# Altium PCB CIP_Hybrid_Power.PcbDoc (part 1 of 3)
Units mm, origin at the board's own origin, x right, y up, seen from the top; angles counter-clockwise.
Board outline 70 x 70 mm, 4 copper layers (Top Layer, GND Pour Layer, Signal Layer 1, Bottom Layer), stack 1.68 mm thick; 202 components, 120 nets, 578 pads, 363 vias.
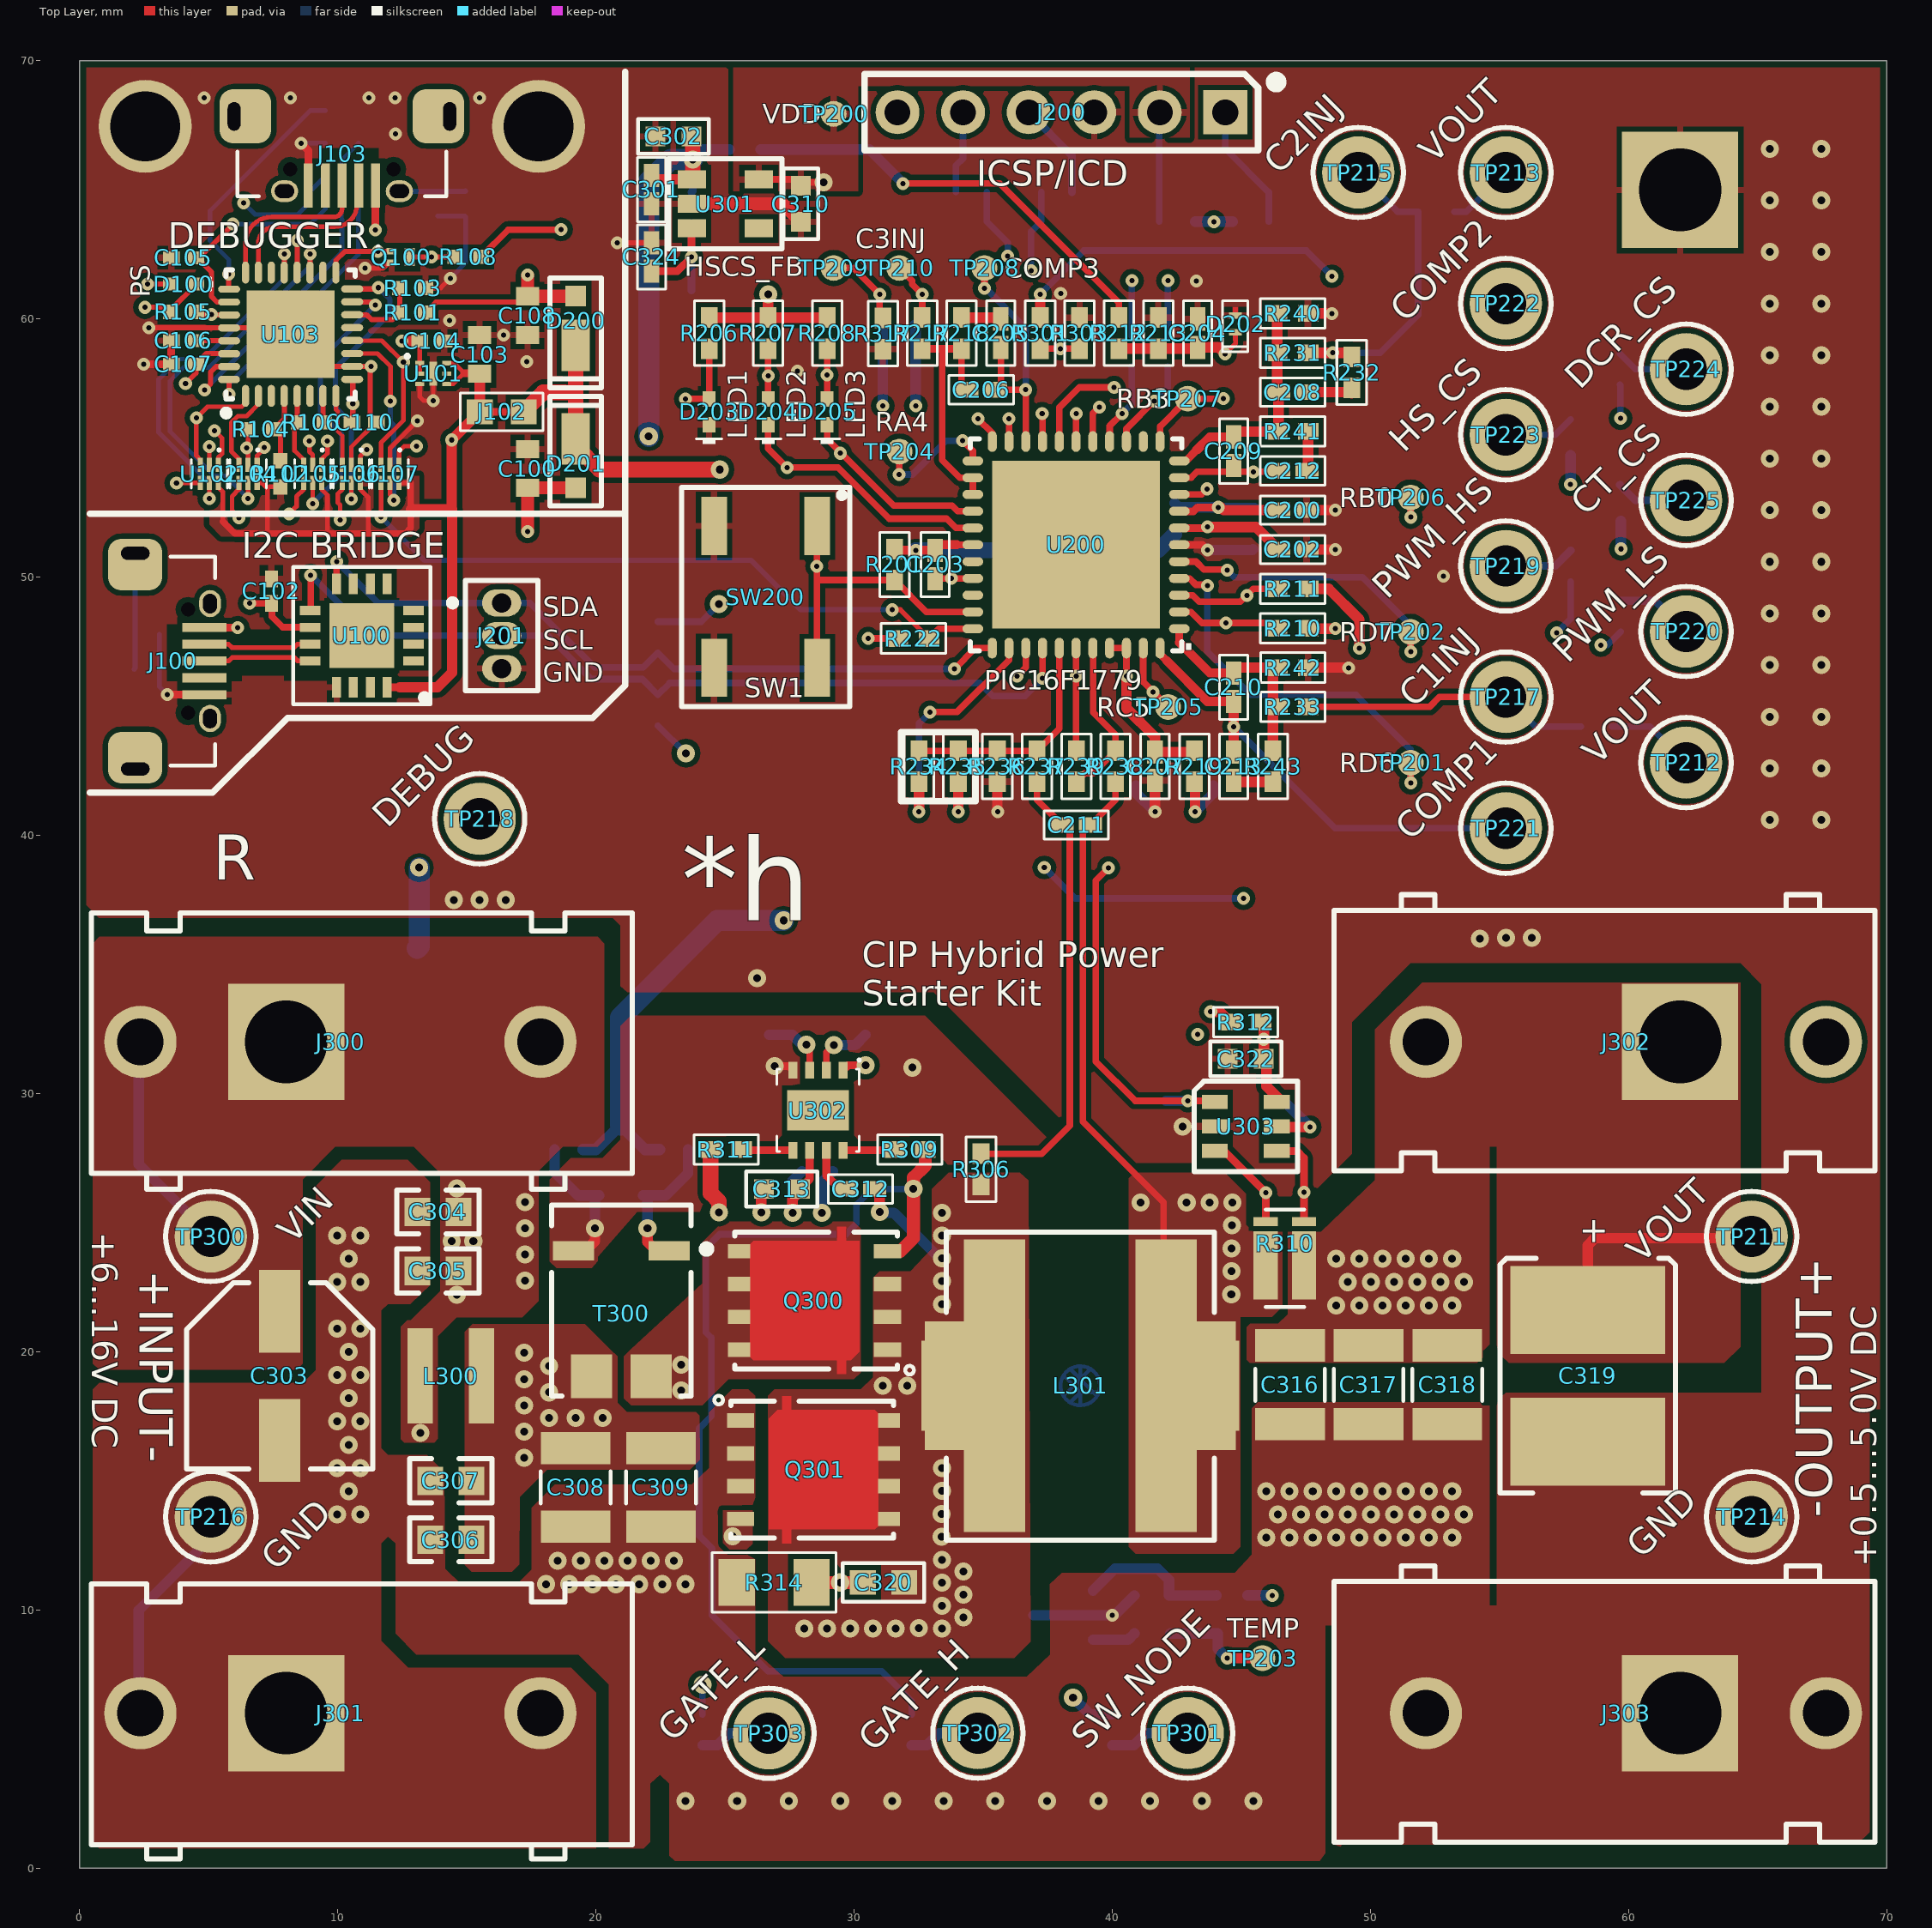
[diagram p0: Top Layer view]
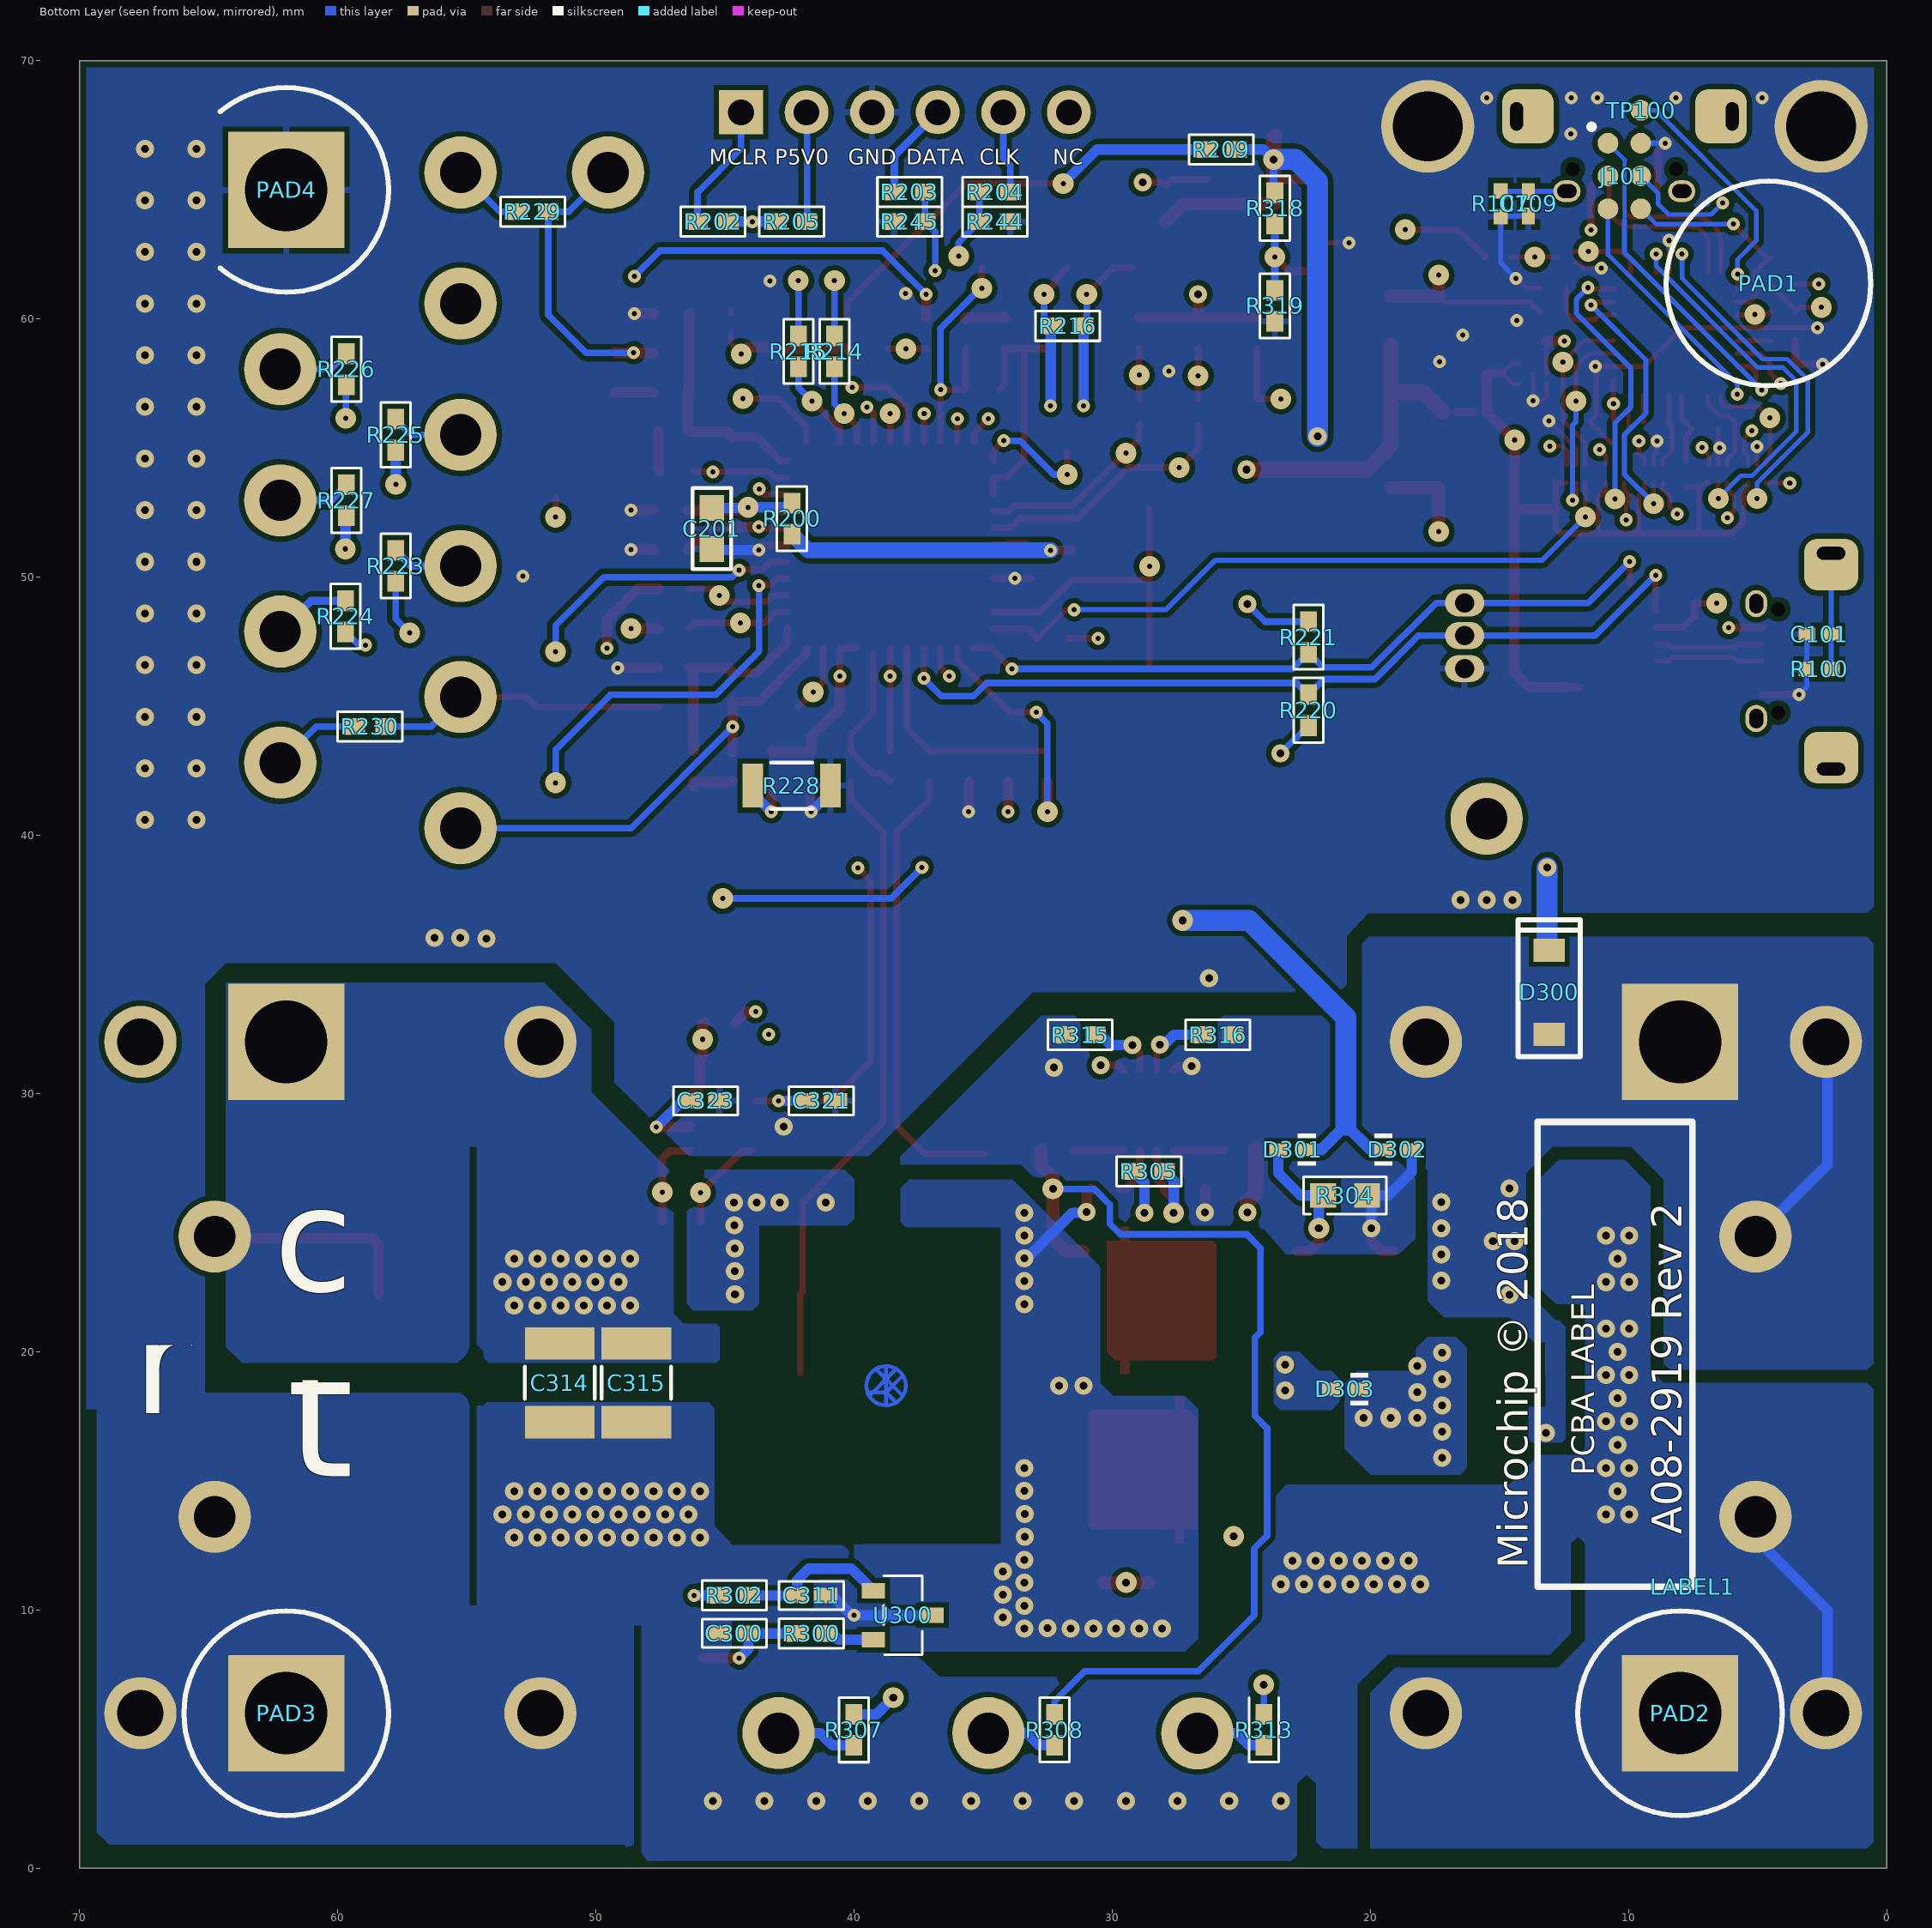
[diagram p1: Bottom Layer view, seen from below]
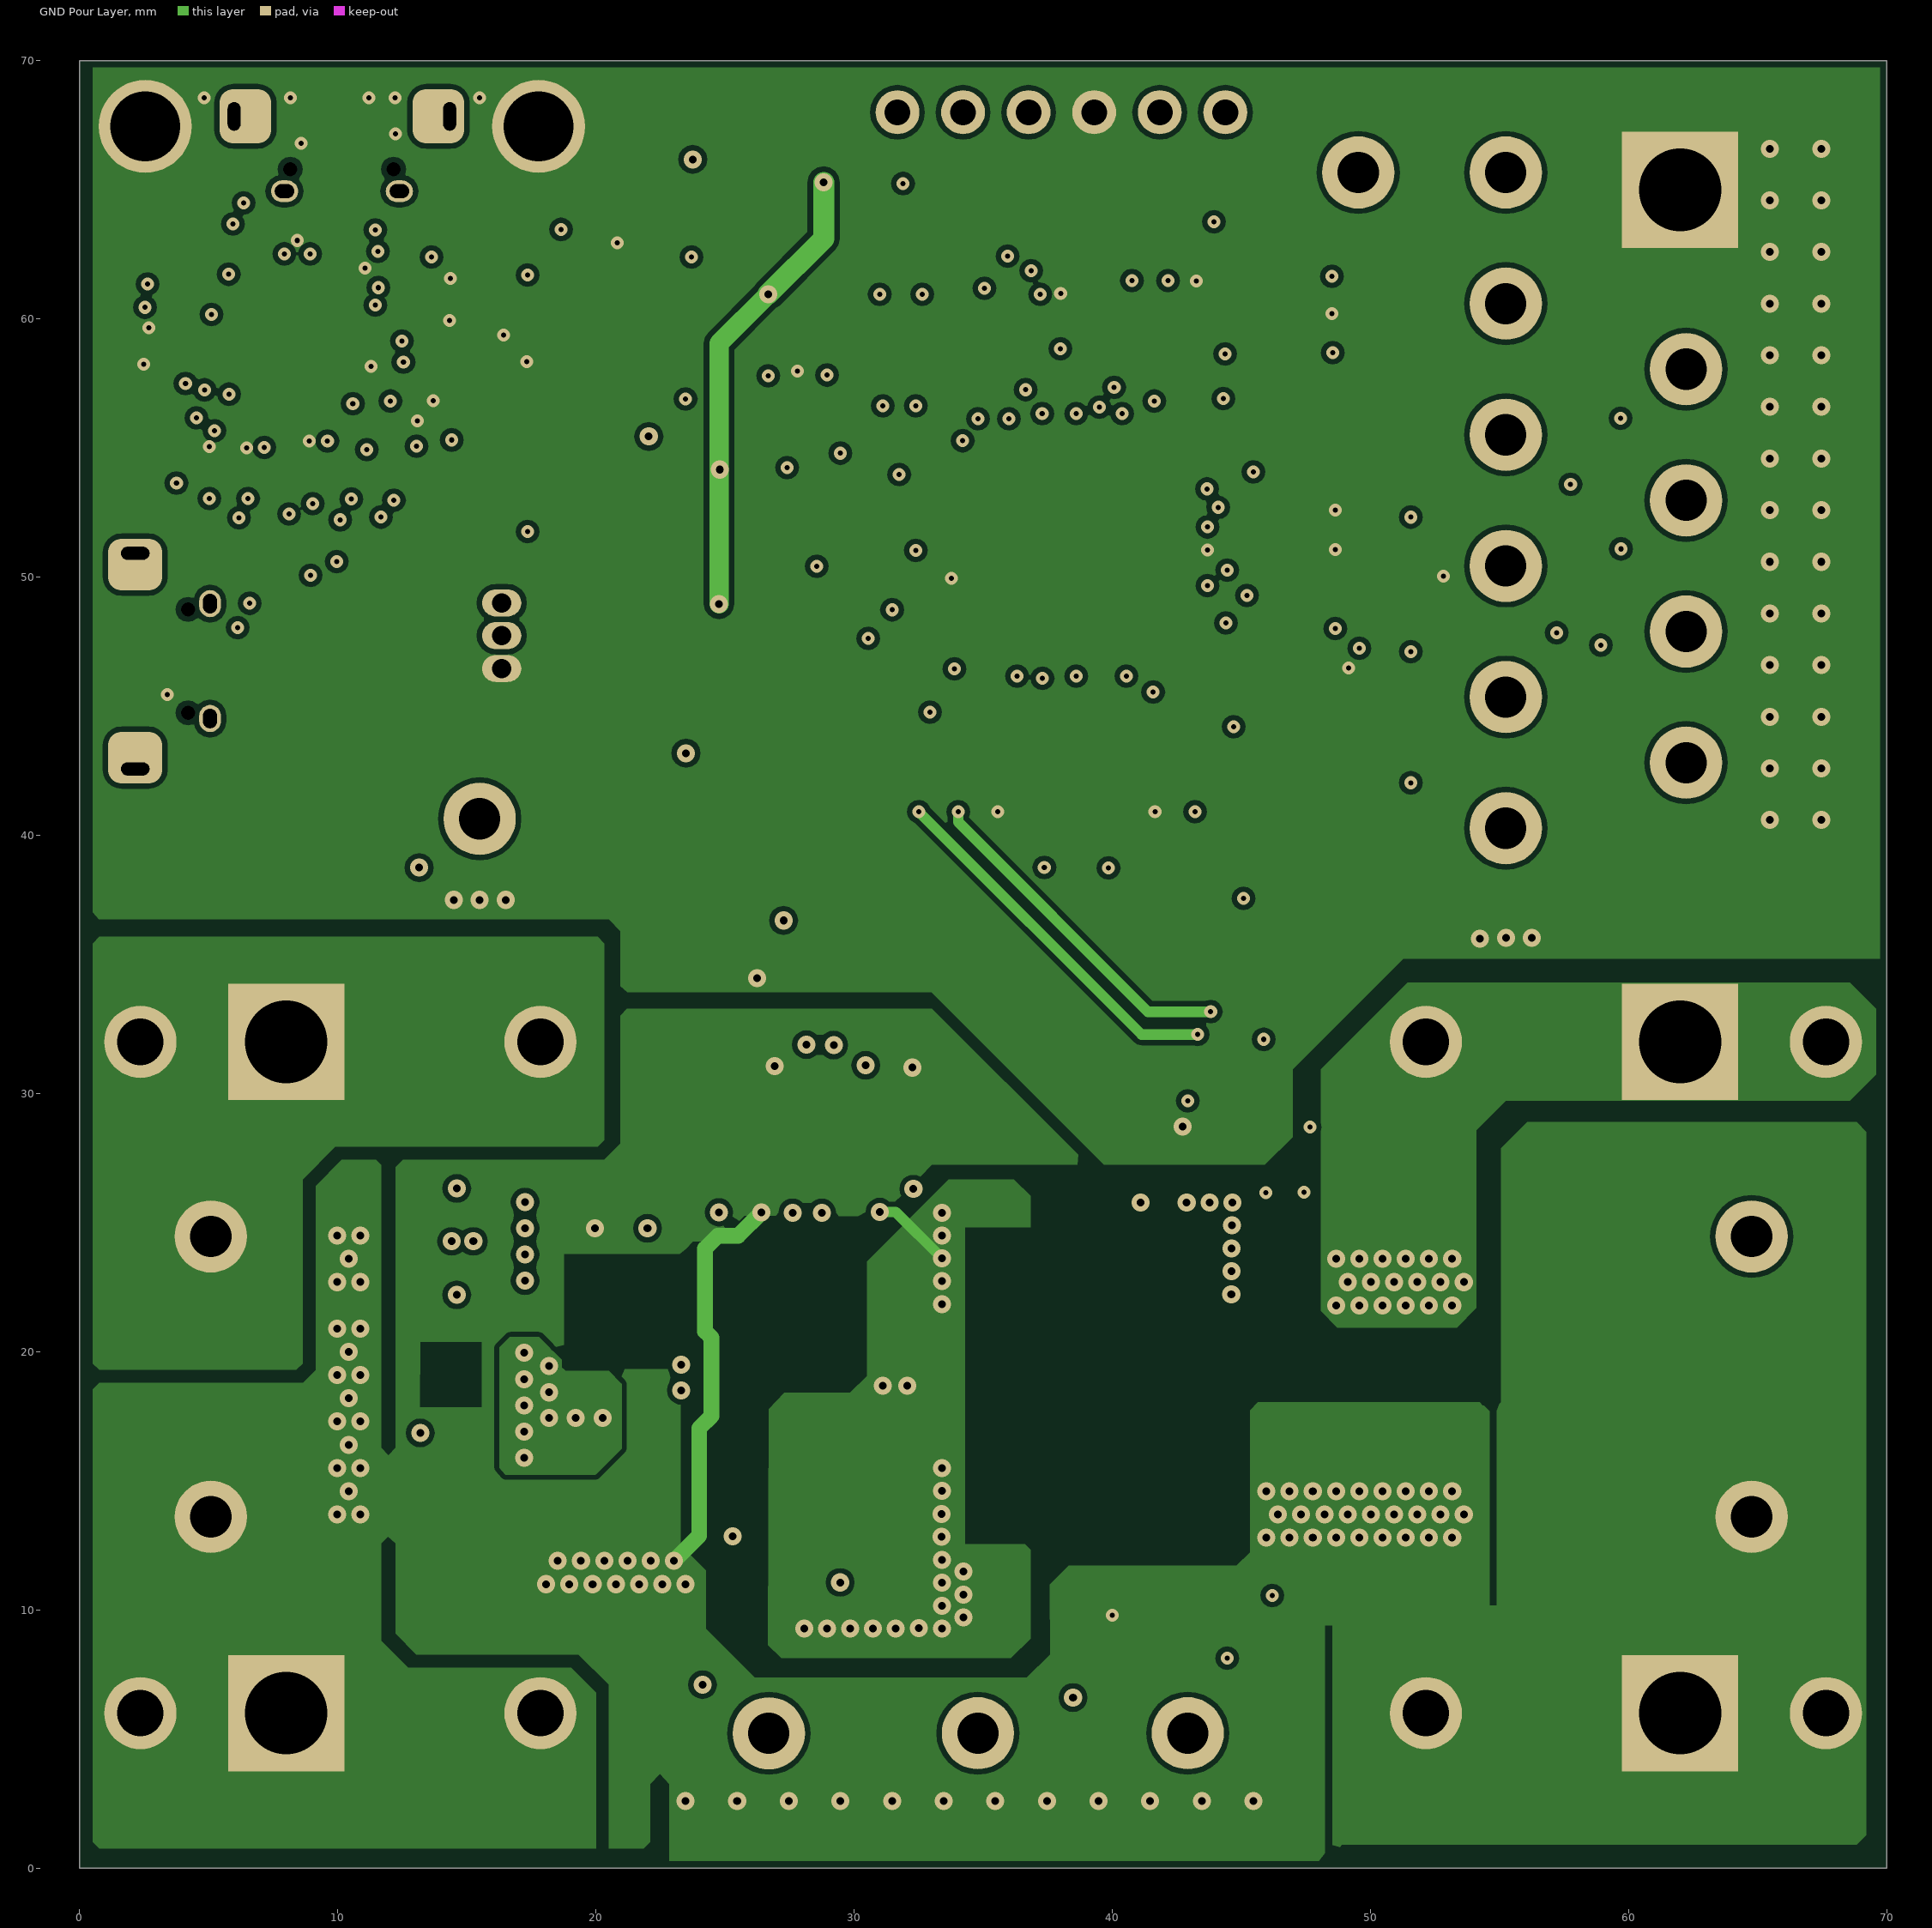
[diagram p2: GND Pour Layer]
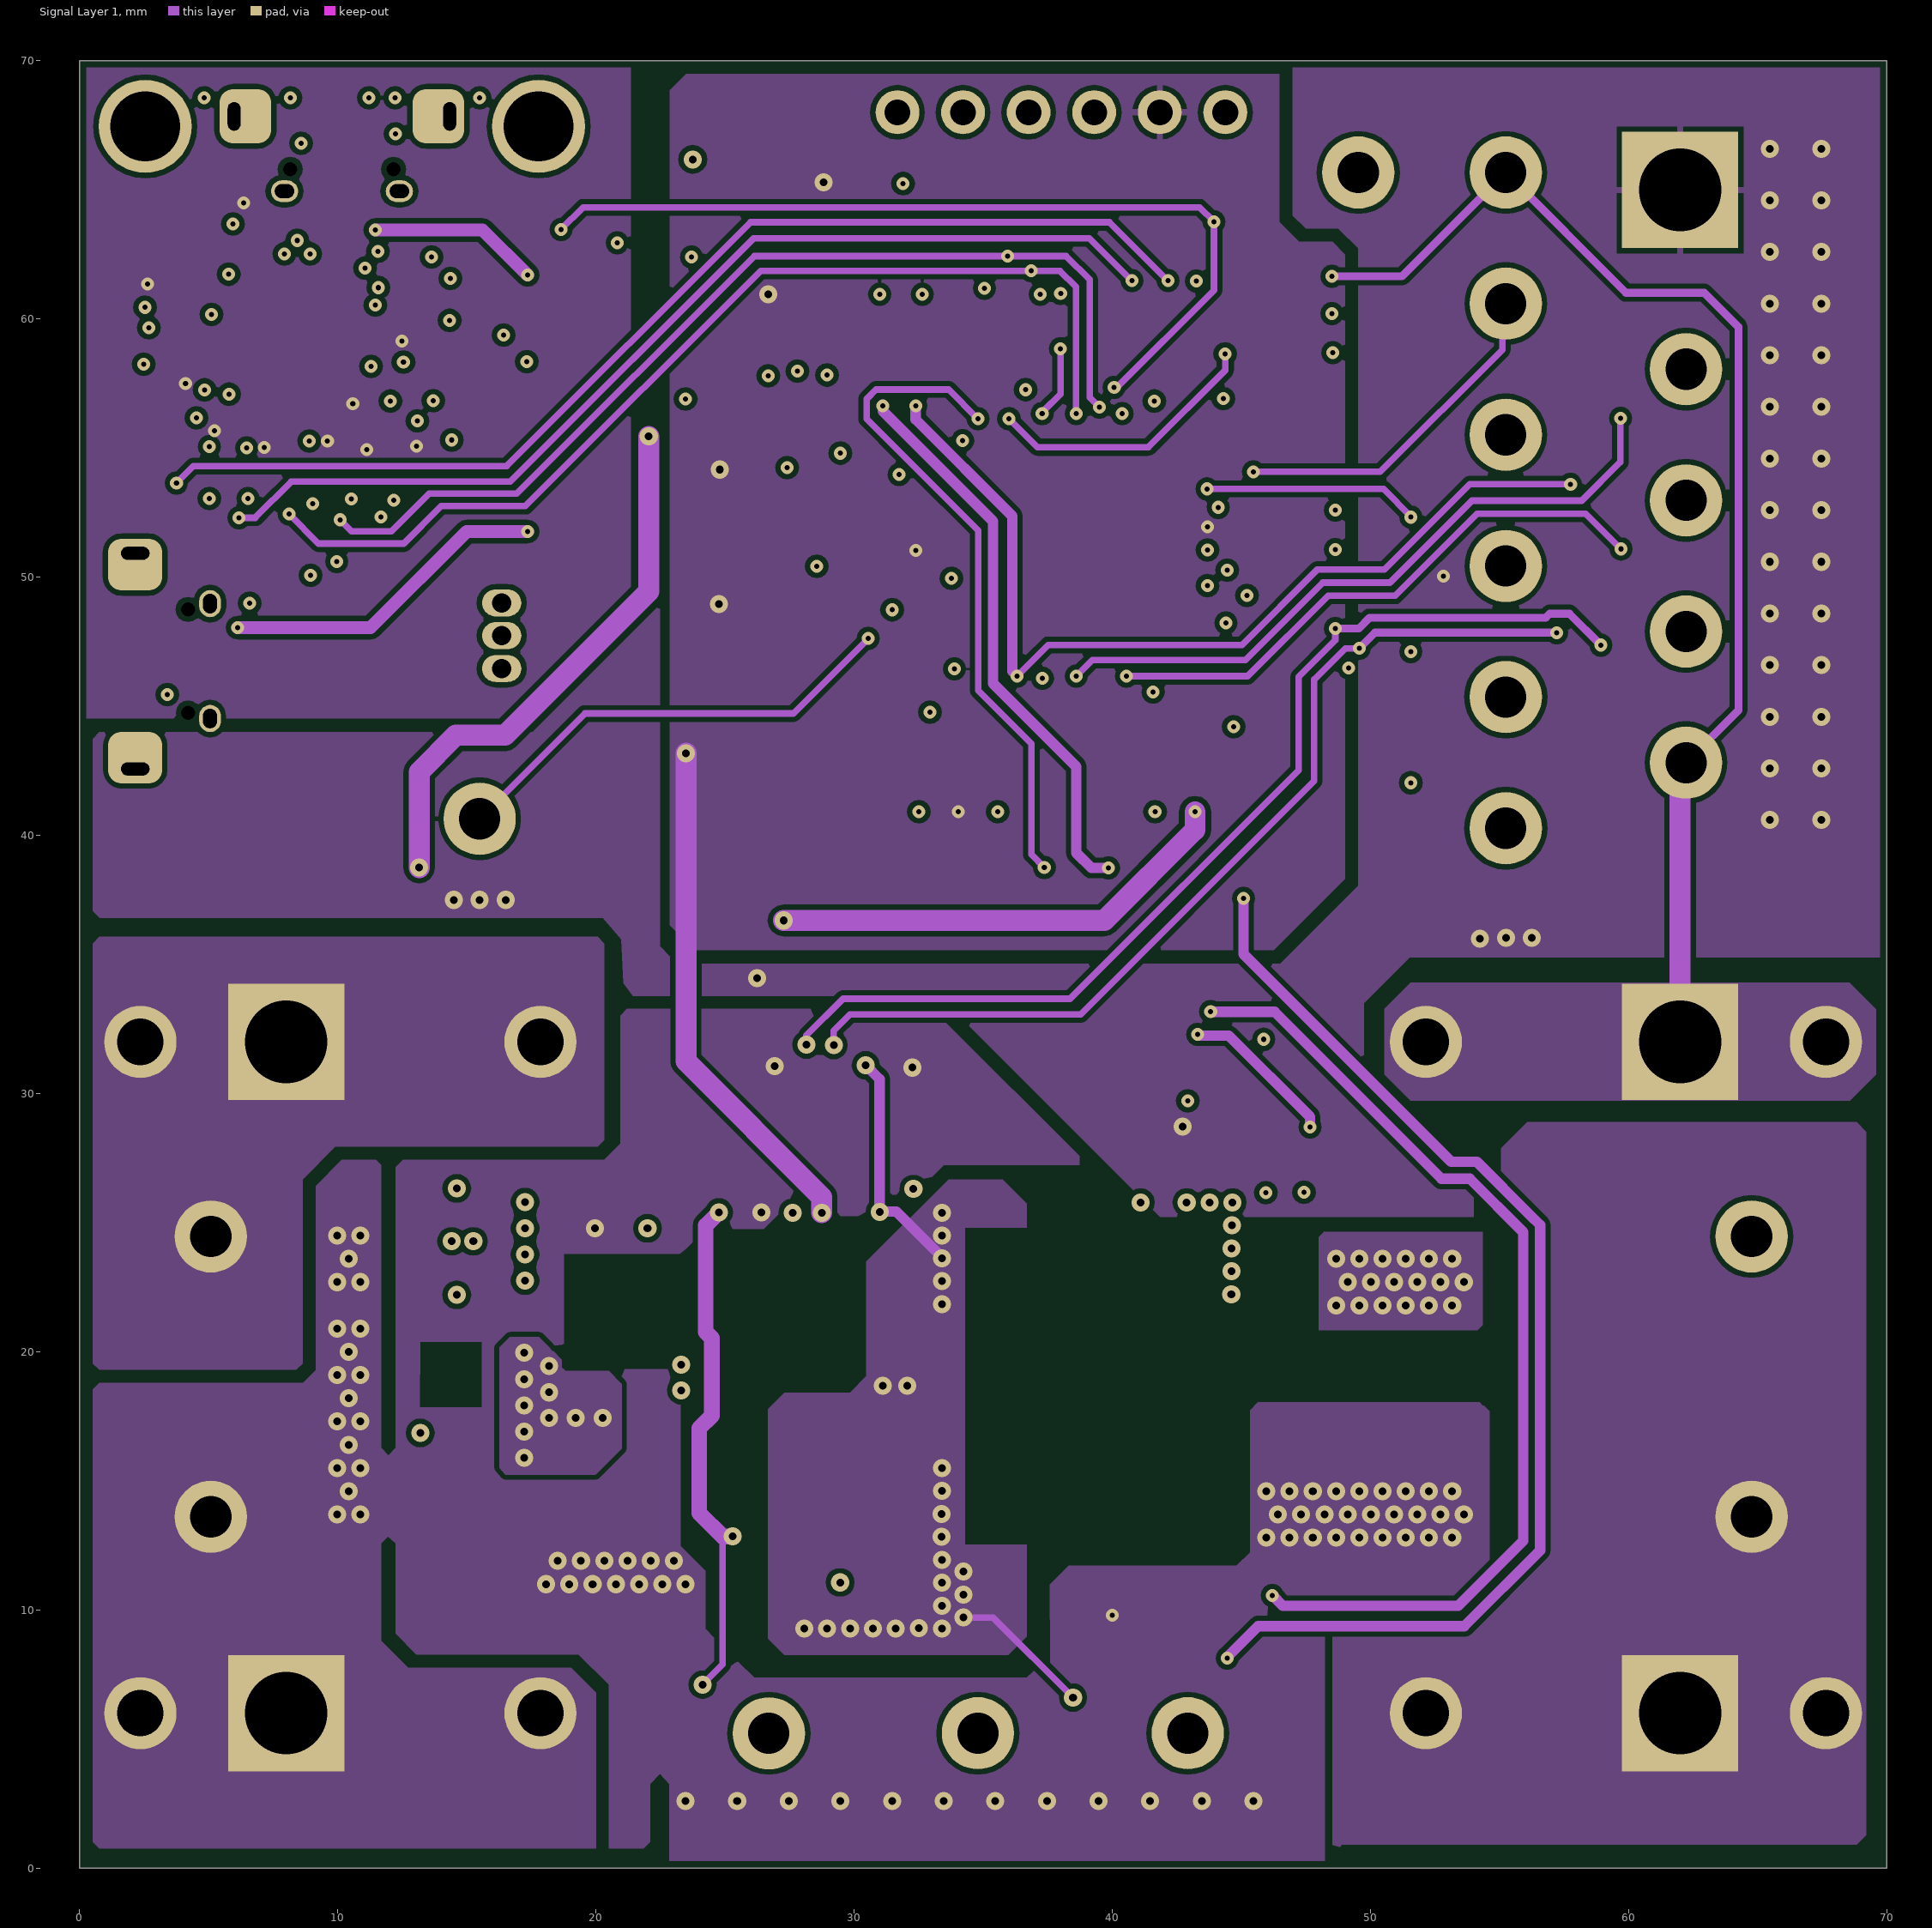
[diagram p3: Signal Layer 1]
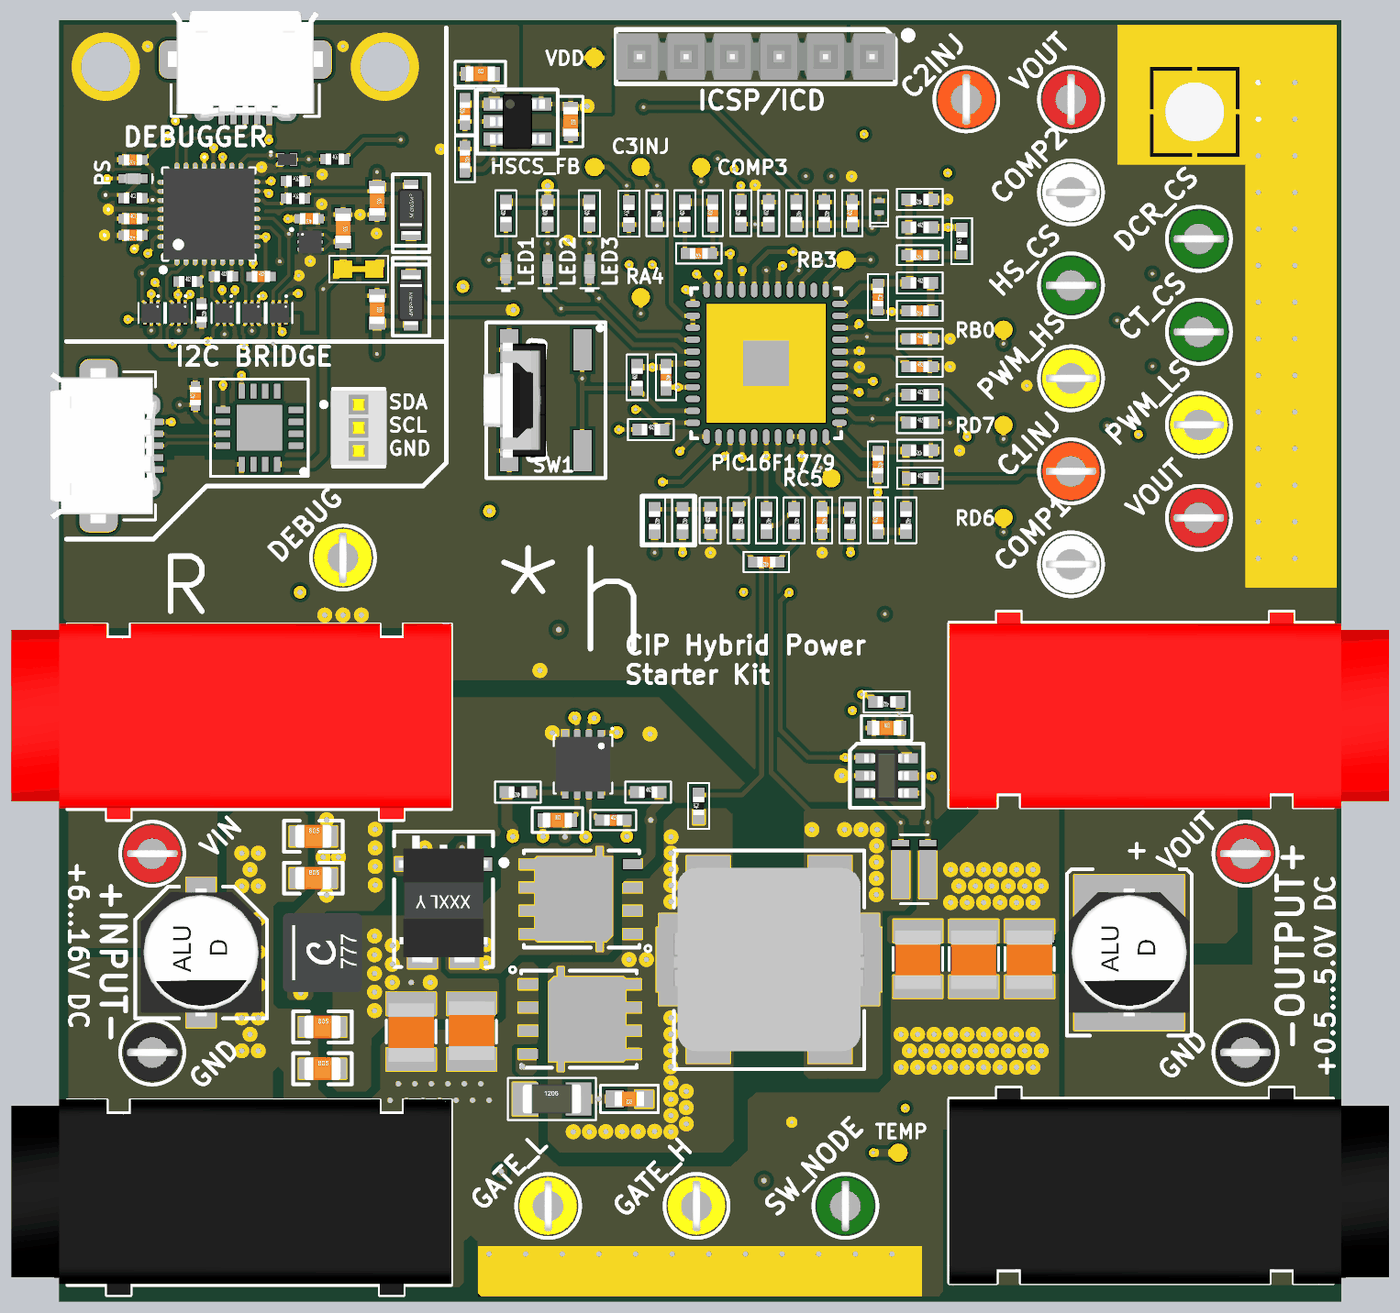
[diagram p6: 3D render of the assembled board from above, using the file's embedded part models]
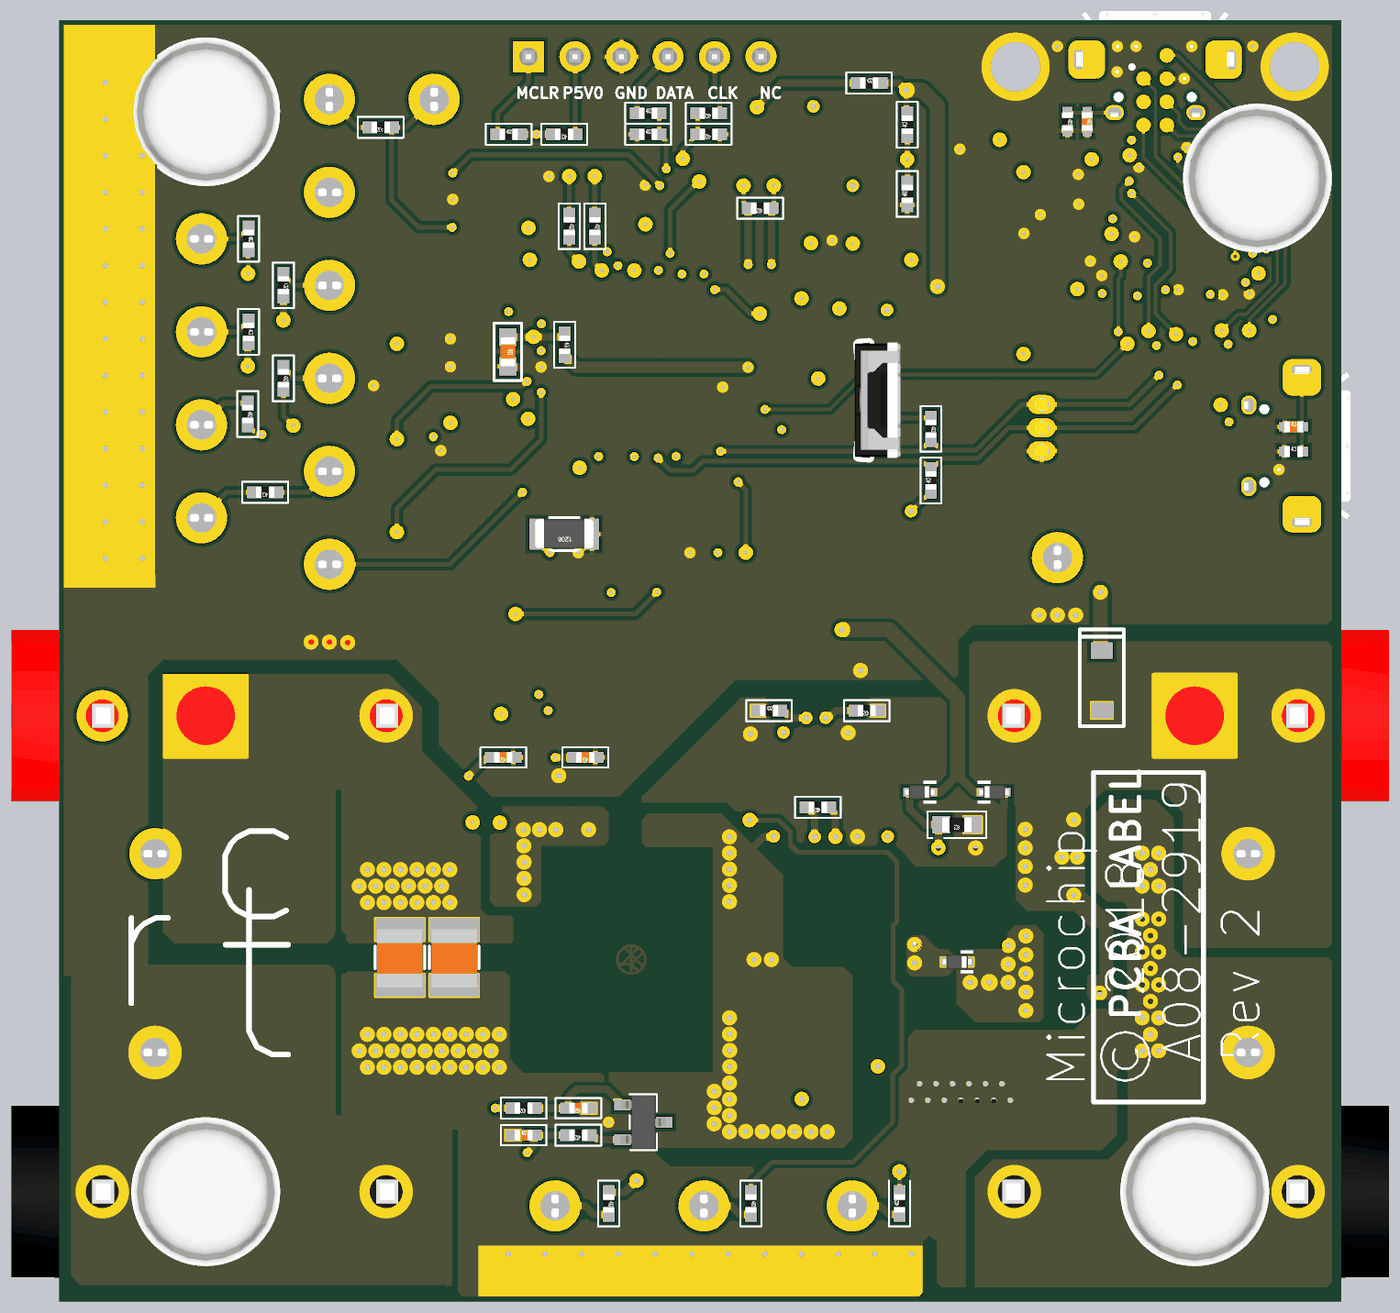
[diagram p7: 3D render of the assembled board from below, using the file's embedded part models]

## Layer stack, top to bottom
Top Solder: solder mask 0.01, Solder Resist, Dk 3.5
Top Layer: signal copper 0.035
Dielectric 1: prepreg 0.27, FR-4, Dk 4.4
GND Pour Layer: signal copper 0.035
Dielectric 6: core 1, FR-4, Dk 4.4
Signal Layer 1: signal copper 0.035
Dielectric 5: prepreg 0.27, FR-4, Dk 4.4
Bottom Layer: signal copper 0.035
Bottom Solder: solder mask 0.01, Solder Resist, Dk 3.5

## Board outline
0,0 70,0 70,70 0,70

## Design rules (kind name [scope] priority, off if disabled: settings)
AcuteAngle [All] p1: minimum=8.00000000000000E+0001 checktracksonly=TRUE
AssemblyTestPointUsage "Schematic Assembly Testpoint Usage_39" [InNet('S0_3_CLK')] p1: valid=1
AssemblyTestPointUsage "Schematic Assembly Testpoint Usage_34" [InNet('S1_1_RX')] p2: valid=1
AssemblyTestPointUsage "Schematic Assembly Testpoint Usage_27" [InNet('NetC312_1')] p3: valid=1
AssemblyTestPointUsage "Schematic Assembly Testpoint Usage_26" [InNet('NetC311_2')] p4: valid=1
AssemblyTestPointUsage "Schematic Assembly Testpoint Usage_24" [InNet('NetD303_2')] p5: valid=1
AssemblyTestPointUsage "Schematic Assembly Testpoint Usage_23" [InNet('NetR309_1')] p6: valid=1
AssemblyTestPointUsage "Schematic Assembly Testpoint Usage_22" [InNet('NetR311_1')] p7: valid=1
AssemblyTestPointUsage "Schematic Assembly Testpoint Usage_21" [InNet('NetR300_1')] p8: valid=1
AssemblyTestPointUsage "Schematic Assembly Testpoint Usage_17" [InNet('VCC_MCU_CORE')] p9: valid=1
AssemblyTestPointUsage "Schematic Assembly Testpoint Usage_11" [InNet('S0_0_RX')] p10: valid=1
AssemblyTestPointUsage "Schematic Assembly Testpoint Usage_10" [InNet('S0_2_TX')] p11: valid=1
AssemblyTestPointUsage "Schematic Assembly Testpoint Usage_9" [InNet('USB2D_N')] p12: valid=1
AssemblyTestPointUsage "Schematic Assembly Testpoint Usage_8" [InNet('USB2D_P')] p13: valid=1
AssemblyTestPointUsage "Schematic Assembly Testpoint Usage_7" [InNet('USBD_N')] p14: valid=1
AssemblyTestPointUsage "Schematic Assembly Testpoint Usage_6" [InNet('USBD_P')] p15: valid=1
AssemblyTestPointUsage "Schematic Assembly Testpoint Usage_5" [InNet('VBUS_ADC')] p16: valid=1
AssemblyTestPointUsage "Schematic Assembly Testpoint Usage_4" [InNet('VTG_ADC')] p17: valid=1
AssemblyTestPointUsage [All] p18: valid=2 allowmultiple=TRUE
AssemblyTestpoint AssemblyTestpoint_Bottom [OnBottomLayer and IsComponent] p1: testpointundercomponent=TRUE minsize=0.8 maxsize=2 preferedsize=0.8 minholesize=0 maxholesize=1 preferedholesize=0.25 testpointgrid=0.025 usegrid=FALSE gridtolerance=0 allowsidebottom=TRUE minspacing=1.27 compbodyclearance=1.27
AssemblyTestpoint [All] p2: testpointundercomponent=TRUE minsize=0.8 maxsize=4 preferedsize=0.8 minholesize=0 maxholesize=2 preferedholesize=0.25 testpointgrid=0.025 usegrid=FALSE gridtolerance=0 allowsidebottom=TRUE minspacing=1.27
BoardOutlineClearance [All] p1: gap=0.25 ignorepadtopadclearanceinfootprint=FALSE
Clearance Clearance_Poly_Impedance [IsRegion vs InDifferentialPairClass('All Differential Pairs')] p1: gap=0.6 ignorepadtopadclearanceinfootprint=FALSE
Clearance Clearance_Poly [InPoly] p2: gap=0.2 ignorepadtopadclearanceinfootprint=FALSE
Clearance "Net to Polygon 0.5mm" [InNet('VCC_P5V0') vs (IsRegion)] p3: gap=0.3 ignorepadtopadclearanceinfootprint=FALSE
Clearance "Pad to Pad 0.2mm" [(IsTrack) or (InPadClass('All Pads')) vs HasFootprint('QFN-40_5x5','TQFP-100_14x14')] p4: gap=0.2 ignorepadtopadclearanceinfootprint=FALSE except(0: Arc-Hole Track-Hole SMDPad-Hole THPad-Hole Via-Hole Fill-Hole Poly-Hole Region-Hole Text-Hole)
Clearance [All] p5: gap=0.15 ignorepadtopadclearanceinfootprint=FALSE
ComponentClearance ComponentClearance_BETWEEN_TESTPOINTS [InComponentClass('Testpoints') or HasFootprint('AP8-01149') vs InComponentClass('Testpoints') or HasFootprint('AP8-01149')] p1: gap=0 collisioncheckmode=3 verticalgap=0 showdistances=FALSE
ComponentClearance ComponentClearance_LABEL [InComponent('LABEL1')] p2: gap=0 collisioncheckmode=3 verticalgap=0 showdistances=FALSE
ComponentClearance ComponentClearance_BOOT [InComponent('TP100') vs InComponent('J101')] p3: gap=0 collisioncheckmode=3 verticalgap=0 showdistances=FALSE
ComponentClearance [All] p4: gap=0.254 collisioncheckmode=3 verticalgap=0.254 showdistances=TRUE
DiffPairsRouting [All] p1: maxlimit=0.22 minlimit=0.2 mostfreqgap=0.2 toplayer_minwidth=0.18 toplayer_maxwidth=0.18 toplayer_prefwidth=0.18 midlayer1_minwidth=0.18 midlayer1_maxwidth=0.18 midlayer1_prefwidth=0.18 midlayer2_minwidth=0.18 midlayer2_maxwidth=0.18 midlayer2_prefwidth=0.18 bottomlayer_minwidth=0.18 bottomlayer_maxwidth=0.18 bottomlayer_prefwidth=0.18 maxuncoupledlength=20
FabricationTestPointUsage TestPointUsage [All] p1: valid=2 allowmultiple=TRUE
FabricationTestpoint Testpoint [All] p1: side=2 testpointundercomponent=TRUE minsize=0.55 maxsize=4 preferedsize=0.8 minholesize=0 maxholesize=2 preferedholesize=0.25 testpointgrid=0 allowsidebottom=TRUE usegrid=FALSE gridtolerance=0 minspacing=1.27
HoleSize [All] p1: absolutevalues=TRUE maxlimit=5 minlimit=0.2 maxpercent=80.000 minpercent=20.000
HoleToHoleClearance HoleToHoleClearance_NPTH [(HoleDiameter > 0) And (PadIsPlated = 'False')] p1: gap=0.25 allowstackedmicrovias=TRUE
HoleToHoleClearance [All] p2: gap=0.3 allowstackedmicrovias=TRUE
MinimumAnnularRing [All] p1: minimumring=0.15
MinimumSolderMaskSliver [All] p1: minsoldermaskwidth=0.08
NetAntennae [Not IsTestpoint] p1: netantennaetolerance=0
PlaneClearance [All] p1: clearance=0.7
PlaneConnect PlaneConnect_Special [HasPad('Free-666')] p1: planeconnectstyle=Direct reliefexpansion=0.508 reliefentries=4 reliefconductorwidth=0.254 reliefairgap=0.254
PlaneConnect [All] p2: pad.planeconnectstyle=Relief pad.reliefexpansion=0.508 pad.reliefentries=4 pad.reliefconductorwidth=0.254 pad.reliefairgap=0.254 via.planeconnectstyle=Direct via.reliefexpansion=0.508 via.reliefentries=4 via.reliefconductorwidth=0.254 via.reliefairgap=0.254
PolygonConnect PolygonConnect_Special [HasPad('Free-666') OR HasFootprint('AP8-00870')] p1: connectstyle=Direct reliefconductorwidth=0.254 reliefentries=4 polygonreliefangle="90 Angle" airgapwidth=0.254
PolygonConnect PolygonConnect_full [All vs IsNamedPolygon('full')] p2: connectstyle=Direct reliefconductorwidth=0 reliefentries=4 polygonreliefangle="90 Angle" airgapwidth=0.254
PolygonConnect [All] p3: thpad.connectstyle=Relief thpad.reliefconductorwidth=0.254 thpad.reliefentries=4 thpad.polygonreliefangle="90 Angle" thpad.airgapwidth=0.2 smdpad.connectstyle=Relief smdpad.reliefconductorwidth=0.254 smdpad.reliefentries=4 smdpad.polygonreliefangle="90 Angle" smdpad.airgapwidth=0.2 via.connectstyle=Direct via.reliefconductorwidth=0.254 via.reliefentries=4 via.polygonreliefangle="90 Angle" via.airgapwidth=0.2
RoutingVias [All] p1: holewidth=0.25 width=0.55 viastyle="Through Hole" minholewidth=0.2 minwidth=0.5 maxholewidth=0.5 maxwidth=1
SMDNeckDown [All] p1: percent=98.000
SilkToSilkClearance SilkToSilkClearance_Text [IsText] p1: silktosilkclearance=0
SilkToSilkClearance [All] p2: silktosilkclearance=0.1
SilkToSolderMaskClearance SilkscreenOverComponentPads_Soldermask [All] p1: minsilkscreentomaskgap=0.12 clearancetoexposedcopper=FALSE
SilkToSolderMaskClearance SilkscreenOverComponentPads_Copper [All] p2: minsilkscreentomaskgap=0.2 clearancetoexposedcopper=TRUE
SilkToSolderMaskClearance SilkscreenOverComponentPads [IsPad] p3: minsilkscreentomaskgap=0.2 clearancetoexposedcopper=FALSE
SolderMaskExpansion SolderMaskTenting [IsVia AND NOT (IsFabTestpoint OR IsAssyTestpoint)] p1: expansion=-1
SolderMaskExpansion [All] p2: expansion=0.06
UnRoutedNet [All] p1: checkbadconnections=TRUE
ViasUnderSMD ViasUnderSMD_GND [InPadClass('Ground_Pads')] p1: allowed=TRUE
ViasUnderSMD ViasUnderSMD_Testpoint [InNet('BOOT') or InNet('GND')] p2: allowed=TRUE
ViasUnderSMD [All] p3: allowed=FALSE
Width Width_Power [InNetClass('Power')] p1: maxlimit=0.5 minlimit=0.175 preferedwidth=0.25
Width [All] p2: maxlimit=10 minlimit=0.15 preferedwidth=0.15
15 further rules are at their usual default settings.

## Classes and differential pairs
component class USB: C100 C101 C102 C103 C104 C105 C106 C107 C108 C109 C110 D100 J100 J101 J102 J103 Q100 R100 R101 R102 R103 R104 R105 R106 R107 R108 TP100 U100 U101 U102 U103 U104 U105 U106 U107
component class CIP_Hybrid_Power_TopLevel: LABEL1 PAD1 PAD2 PAD3 PAD4
component class MCU: C200 C201 C202 C203 C204 C205 C206 C207 C208 C209 C210 C211 C212 C213 D200 D201 D202 D203 D204 D205 J200 J201 R200 R201 R202 R203 R204 R205 R206 R207 R208 R209 R210 R211 R212 R213 R214 R215 R216 R217 R218 R219 R220 R221 R222 R223 R224 R225 R226 R227 R228 R229 R230 R231 R232 R233 R234 R235 R236 R237 R238 R239 R240 R241 R242 R243 R244 R245 SW200 TP200 TP201 TP202 TP203 TP204 TP205 TP206 TP207 TP208 TP209 TP210 TP211 TP212 TP213 TP214 TP215 TP216 TP217 TP218 TP219 TP220 TP221 TP222 TP223 TP224 TP225 U200
component class Power: C300 C301 C302 C303 C304 C305 C306 C307 C308 C309 C310 C311 C312 C313 C314 C315 C316 C317 C318 C319 C320 C321 C322 C323 C324 D300 D301 D302 D303 J300 J301 J302 J303 L300 L301 Q300 Q301 R300 R301 R302 R303 R304 R305 R306 R307 R308 R309 R310 R311 R312 R313 R314 R315 R316 R317 R318 R319 T300 TP300 TP301 TP302 TP303 U300 U301 U302 U303
differential pair USBD: +USBD_P -USBD_N
differential pair USB2D: +USB2D_P -USB2D_N

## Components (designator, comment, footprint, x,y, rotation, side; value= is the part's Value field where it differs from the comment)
C100 "" AP1-00096 17.35,54.208 r270 top value=4.7uF
C101 "" AP1-00053 2.608,47.791 r180 bottom value=100nF
C102 "" AP1-00053 7.425,49.46 r90 top value=470nF
C103 "" AP1-00096 15.494,58.626 r270 top value=4.7uF
C104 "Farnell no: 1288200" AP1-00053 13.65,59.152 r180 top value=2.2uF
C105 "" AP1-00053 4.025,62.375 r180 top value=100nF
C106 "" AP1-00053 4.025,59.164 r0 top value=1u
C107 "" AP1-00053 4.025,58.252 r180 top value=100nF
C108 "" AP1-00096 17.35,60.131 r270 top value=4.7uF
C109 "" AP1-00053 13.875,64.463 r270 bottom value=100nF
C110 "" AP1-00053 11.025,56 r0 top locked value=100nF
C200 "" AP1-00001 46.99,52.594 r0 top value=100nF
C201 "" AP1-00002 45.512,51.883 r270 bottom value=10uF
C202 "" AP1-00001 46.99,51.07 r0 top value=100nF
C203 "" AP1-00001 33.139,50.491 r270 top value=100nF
C204 "" AP1-00001 43.307,59.452 r90 top value=100nF
C205 "" AP1-00001 35.687,59.452 r90 top value=100nF
C206 "" AP1-00001 34.925,57.259 r180 top value=100nF
C207 "" AP1-00001 41.656,42.672 r270 top value=68p
C208 "" AP1-00001 46.99,57.166 r180 top value=4.7nF
C209 "" AP1-00001 44.7,54.88 r270 top value=130pF
C210 "" AP1-00001 44.704,45.736 r270 top value=33p
C211 "" AP1-00001 38.608,40.402 r180 top value=100nF
C212 "" AP1-00001 46.99,54.118 r180 top value=6.8nF
C213 "" AP1-00001 44.704,42.672 r90 top value=1nF
C300 "" AP1-00001 44.642,9.087 r180 bottom value=100nF
C301 "" AP1-00001 22.152,65.011 r90 top value=1nF
C302 "" AP1-00039 23,67.075 r0 top value=1uF
C303 "" AP1-00028 7.747,19.066 r270 top value=47uF/35V
C304 "" AP1-00097 13.877,25.413 r0 top value=10uF/35V
C305 "" AP1-00097 13.877,23.127 r0 top value=10uF/35V
C306 "" AP1-00097 14.377,12.713 r0 top value=10uF/35V
C307 "" AP1-00097 14.377,14.999 r0 top value=10uF/35V
C308 "" AP1-00015 19.215,14.745 r90 top value=10u
C309 "" AP1-00015 22.517,14.745 r270 top value=10u
C310 "" AP1-00039 27.932,64.461 r270 top value=2.2uF
C311 "" AP1-00001 41.656,10.557 r0 bottom value=100nF
C312 "" AP1-00001 30.25,26.302 r0 top value=100nF
C313 "" AP1-00039 27.202,26.302 r0 top value=4.7uF
C314 "" AP1-00015 51.402,18.796 r90 bottom value=22u/25V
C315 "" AP1-00015 48.434,18.796 r90 bottom value=22u/25V
C316 "" AP1-00015 46.886,18.717 r90 top value=100uF/16V
C317 "" AP1-00015 49.934,18.717 r90 top value=100uF/16V
C318 "" AP1-00015 52.982,18.717 r90 top value=100uF/16V
C319 "" AP1-00028 58.42,19.066 r270 top locked value=47uF/35V
C320 "" AP1-00002 31.139,11.062 r180 top value=1.5n
C321 "" AP1-00001 41.275,29.718 r0 bottom value=100pF
C322 "" AP1-00039 45.175,31.341 r0 top value=2.2uF
C323 "" AP1-00001 45.75,29.718 r0 bottom value=100nF
C324 "" AP1-00001 22.152,62.404 r270 top value=100nF
D100 "" AP4-00160 4.025,61.349 r180 top value="GREEN LED"
D200 "" AP4-00063 19.218,59.933 r90 top value=MSS2P3
D201 "" AP4-00063 19.218,54.408 r270 top value=MSS2P3
D202 "" AP4-00048 44.776,59.809 r90 top value=VESD03A1B-HD1
D203 "" AP4-00160 24.384,56.404 r90 top value="GREEN LED"
D204 "" AP4-00160 26.67,56.404 r90 top value="RED LED"
D205 "" AP4-00160 28.956,56.404 r90 top value="BLUE LED"
D300 "" AP4-00012 13.073,33.925 r90 bottom value=PMEG4030ER
D301 "" AP4-00084 23.013,27.826 r0 bottom value=BAS516
D302 "" AP4-00084 18.949,27.826 r180 bottom value=BAS516
D303 "" AP4-00084 20.975,18.55 r0 bottom value=BAS516
J100 "" AP8-01099 2.15,46.75 r270 top locked value=MU-MB0142AB2-269
J101 "" AP8-00997 10.16,64.27 r270 bottom locked value="Testpoint Array"
J102 "" AP9-00044 16.35,56.404 r0 top net-tie value=SMD-STRAP_0603_CLOSED
J103 "" AP8-01099 10.16,67.85 r180 top locked value=MU-MB0142AB2-269
J200 "" AP8-00676 38.031,68.008 r180 top locked value=HMTSW-106-23-F-S-237
J201 "" AP8-01113 16.35,47.734 r270 top value=SLM-103-01-L-S
J300 "" AP8-01144 10.1,32 r0 top locked value="Banana Test Connector, 4mm, Socket, Red"
J301 "" AP8-01145 10.1,6 r0 top locked value="Banana Test Connector, 4mm, Socket, Black"
J302 "" AP8-01144 59.9,32 r180 top locked value="Banana Test Connector, 4mm, Socket, Red"
J303 "" AP8-01145 59.9,6 r180 top locked value="Banana Test Connector, 4mm, Socket, Black"
L300 "Digi-Key: 732-8227-1-ND" AP3-00119 14.377,19.063 r0 top value=680nH
L301 "" AP3-00162 38.763,18.682 r0 top locked value=2.2uH
LABEL1 "" AP8-00317 7.525,10.902 r90 bottom value="Label PCBA"
PAD1 "" AP8-01163 4.575,61.375 r180 bottom value=SJ61A1
PAD2 "" AP8-01163 8,6 r180 bottom value=SJ61A1
PAD3 "" AP8-01163 62,6 r180 bottom value=SJ61A1
PAD4 "" AP8-01163 62,65 r180 bottom locked value=SJ61A1
Q100 "" AP5-00056 12.435,62.4 r0 top value=DMN65D8LFB
Q300 "" AP5-00058 28.524,21.984 r90 top value=MCP87050
Q301 "" AP5-00058 28.379,15.426 r270 top value=MCP87022
R100 "" AP2-00011 2.608,46.441 r180 bottom value=1M
R101 "" AP2-00011 12.9,60.251 r0 top locked value=47k
R102 "" AP2-00011 7.775,54.002 r270 top locked value=47k
R103 "" AP2-00011 12.9,61.201 r0 top locked value=47k
R104 "" AP2-00011 7.024,55.725 r0 top locked value=47k
R105 "" AP2-00011 4.025,60.275 r0 top value=1k
R106 "" AP2-00011 8.974,56 r0 top locked value=1k
R107 "" AP2-00011 14.95,64.463 r270 bottom value=1M
R108 "" AP2-00011 15.05,62.404 r0 top value=49.9R
R200 "" AP2-00000 42.41,52.269 r270 bottom value=4.7R
R201 "" AP2-00000 31.566,50.491 r90 top value=10k
R202 "" AP2-00000 45.466,63.77 r180 bottom value=49.9R
R203 "" AP2-00000 37.846,64.913 r180 bottom value=49.9R
R204 "" AP2-00000 34.544,64.913 r0 bottom value=49.9R
R205 "" AP2-00000 42.418,63.77 r0 bottom value=10k
R206 "" AP2-00000 24.384,59.452 r90 top value=470R
R207 "" AP2-00000 26.67,59.452 r90 top value=1k
R208 "" AP2-00000 28.956,59.452 r90 top value=1k
R209 "" AP2-00000 25.781,66.564 r180 bottom value=100R
R210 "" AP2-00000 46.99,48.022 r0 top value=49.9R
R211 "" AP2-00000 46.99,49.546 r0 top value=49.9R
R212 "" AP2-00000 40.259,59.452 r270 top value=10k
R213 "" AP2-00000 41.783,59.452 r270 top value=1k
R214 "" AP2-00000 40.759,58.746 r270 bottom value=49.9R
R215 "" AP2-00000 42.156,58.746 r270 bottom value=49.9R
R216 "" AP2-00000 31.725,59.728 r0 bottom value=10R
R217 "" AP2-00000 32.639,59.452 r270 top value=0R
R218 "" AP2-00000 34.163,59.452 r90 top value=0R
R219 "" AP2-00000 43.18,42.672 r270 top value=100R
R220 "" AP2-00000 22.401,44.847 r90 bottom value=10k
R221 "" AP2-00000 22.401,47.675 r270 bottom value=10k
R222 "" AP2-00000 32.3,47.628 r0 top value=49.9R
R223 "" AP2-00000 57.757,50.435 r270 bottom value=49.9R
R224 "" AP2-00000 59.703,48.484 r270 bottom value=49.9R
R225 "" AP2-00000 57.757,55.515 r270 bottom value=49.9R
R226 "" AP2-00000 59.666,58.055 r270 bottom value=49.9R
R227 "" AP2-00000 59.666,52.975 r270 bottom value=49.9R
R228 "" AP2-00073 42.418,41.926 r0 bottom value=20R
R229 "" AP2-00000 52.451,64.151 r0 bottom value=10R
R230 "" AP2-00000 58.752,44.212 r0 bottom value=10R
R231 "" AP2-00000 46.99,58.69 r0 top value=5.9k
R232 "" AP2-00000 49.276,57.928 r90 top value=137R
R233 "" AP2-00000 46.997,44.974 r0 top value=5.1k
R234 "" AP2-00000 32.512,42.672 r270 top value=200k
R235 "" AP2-00000 34.036,42.672 r270 top value=100k
R236 "Farnell no: 2073088" AP2-00000 35.548,42.672 r90 top value=49.9k
R237 "" AP2-00000 37.084,42.672 r270 top value=10k
R238 "" AP2-00000 40.132,42.672 r270 top value=10k
R239 "Farnell no: 2073088" AP2-00000 38.608,42.672 r270 top value=49.9k
R240 "" AP2-00000 46.99,60.214 r180 top value=18.2k
R241 "" AP2-00000 46.99,55.642 r0 top value=5.1k
R242 "" AP2-00000 46.997,46.498 r180 top value=15.4k
R243 "" AP2-00000 46.228,42.672 r270 top value=39k
R244 "" AP2-00000 34.544,63.77 r0 bottom value=47k
R245 "" AP2-00000 37.846,63.77 r180 bottom value=47k
R300 "" AP2-00000 41.656,9.087 r0 bottom value=100R
R301 "" AP2-00000 37.211,59.452 r90 top value=10k
R302 "" AP2-00000 44.642,10.561 r0 bottom value=10R
R303 "" AP2-00000 38.735,59.452 r90 top value=10k
R304 "" AP2-00001 20.981,26.048 r0 bottom value=4.7k
R305 "" AP2-00000 28.577,26.988 r0 bottom value=10R
R306 "Farnell no: 2130393" AP2-00000 34.917,27.067 r90 top value=3.32k
R307 "" AP2-00000 40.005,5.35 r270 bottom value=49.9R
R308 "" AP2-00000 32.232,5.353 r270 bottom value=49.9R
R309 "" AP2-00000 32.157,27.826 r0 top value=4.7R
R310 "" AP2-00099 46.687,23.616 r180 top value=0.010R
R311 "" AP2-00000 25.045,27.826 r180 top value=1R
R312 "" AP2-00000 45.174,32.766 r180 top value=10R
R313 "" AP2-00000 24.128,5.353 r90 bottom value=49.9R
R314 "" AP2-00003 26.904,11.062 r0 top value=4.7R
R315 "" AP2-00000 31.242,32.274 r180 bottom value=10k
R316 "" AP2-00000 25.908,32.274 r0 bottom value=10k
R317 "" AP2-00000 31.115,59.436 r90 top value=20k
R318 "" AP2-00000 23.7,64.285 r90 bottom value=5.6k
R319 "" AP2-00000 23.7,60.509 r90 bottom value=4.7k
SW200 "Rating: DC 12V 50mA / Max 0.1 ohm contact resistance" AP8-00137 26.574,49.236 r270 top value=TS604VM1-035CR
T300 "" AP3-00161 20.983,21.476 r270 top value=CST7030-100L
TP100 "PCB implemented component." AP8-00870 9.525,68.08 r0 bottom locked value="SMD Test point - 0.8mm"
TP200 "" AP8-01149 29.21,67.945 r0 top value=TESTPAD
TP201 "" AP8-01149 51.562,42.815 r180 top value=TESTPAD
TP202 "" AP8-01149 51.562,47.879 r180 top value=TESTPAD
TP203 "" AP8-01149 45.824,8.128 r90 top value=TESTPAD
TP204 "" AP8-01149 31.756,54.864 r0 top value=TESTPAD
TP205 "" AP8-01149 42.164,44.974 r90 top value=TESTPAD
TP206 "" AP8-01149 51.562,53.086 r90 top value=TESTPAD
TP207 "" AP8-01149 42.926,56.912 r90 top value=TESTPAD
TP208 "" AP8-01149 35.052,61.976 r90 top value=TESTPAD
TP209 "" AP8-01149 29.21,61.976 r180 top value=TESTPAD
TP210 "" AP8-01149 31.75,61.976 r180 top value=TESTPAD
TP211 "Color keyed test point loop" AP8-01136 64.77,24.464 r90 top locked value="TP LOOP Red"
TP212 "Color keyed test point loop" AP8-01136 62.23,42.815 r90 top locked value="TP LOOP Red"
TP213 "Color keyed test point loop" AP8-01136 55.245,65.675 r180 top locked value="TP LOOP Red"
TP214 "Color keyed test point loop" AP8-01159 64.77,13.605 r270 top value="TP LOOP Black"
TP215 "Color keyed test point loop" AP8-01138 49.53,65.675 r180 top locked value="TP LOOP Orange"
TP216 "Color keyed test point loop" AP8-01159 5.08,13.605 r90 top value="TP LOOP Black"
TP217 "Color keyed test point loop" AP8-01138 55.245,45.355 r90 top locked value="TP LOOP Orange"
TP218 "Color keyed test point loop" AP8-01139 15.494,40.64 r0 top locked value="TP LOOP Yellow"
TP219 "Color keyed test point loop" AP8-01139 55.245,50.435 r90 top locked value="TP LOOP Yellow"
TP220 "Color keyed test point loop" AP8-01139 62.23,47.895 r90 top locked value="TP LOOP Yellow"
TP221 "Color keyed test point loop" AP8-01137 55.245,40.275 r90 top locked value="TP LOOP White"
TP222 "Color keyed test point loop" AP8-01137 55.245,60.595 r90 top locked value="TP LOOP White"
TP223 "Color keyed test point loop" AP8-01140 55.245,55.515 r90 top locked value="TP LOOP Green"
TP224 "Color keyed test point loop" AP8-01140 62.23,58.055 r90 top locked value="TP LOOP Green"
TP225 "Color keyed test point loop" AP8-01140 62.23,52.975 r90 top locked value="TP LOOP Green"
TP300 "Color keyed test point loop" AP8-01136 5.08,24.464 r90 top locked value="TP LOOP Red"
TP301 "Color keyed test point loop" AP8-01140 42.926,5.223 r0 top locked value="TP LOOP Green"
TP302 "Color keyed test point loop" AP8-01139 34.798,5.223 r180 top locked value="TP LOOP Yellow"
TP303 "Color keyed test point loop" AP8-01139 26.696,5.22 r180 top locked value="TP LOOP Yellow"
U100 "" AP6-00483 10.93,47.734 r180 top value=MCP2221AT-I/ML
U101 "" AP6-00481 13.7,57.883 r0 top value=MIC5528-3.3YMT
U102 "" AP6-00505 5.025,54.001 r270 top locked value=74LVC1T45FW4-7
U103 "QFN32" AP6-00418 8.17,59.41 r0 top locked value=SAMD21E18A-MUT
U104 "" AP6-00505 6.525,54.001 r270 top locked value=74LVC1T45FW4-7
U105 "" AP6-00505 9.025,54.001 r270 top locked value=74LVC1T45FW4-7
U106 "" AP6-00505 10.525,54.001 r270 top locked value=74LVC1T45FW4-7
U107 "" AP6-00505 12.025,54.001 r270 top locked value=74LVC1T45FW4-7
U200 "" AP6-00524 38.6,51.253 r180 top value=PIC16F1779-I/ML
U300 "" AP5-00046 38.1,9.795 r180 bottom value=MCP9701AT-E/TT
U301 "2.3V - 36V input" AP6-00014 25.011,64.461 r0 top value=MIC5233-5.0YM5
U302 "" AP6-00527 28.601,29.35 r270 top value=MCP14700-E/MF
U303 "" AP6-00095 45.175,28.728 r0 top value=MCP6C02

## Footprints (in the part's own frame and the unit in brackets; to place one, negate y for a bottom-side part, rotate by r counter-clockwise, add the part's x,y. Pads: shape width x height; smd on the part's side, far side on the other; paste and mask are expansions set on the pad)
AP1-00001 [mm] "Standard 0402 SMD capacitor footprint"
  rect 0.9x0.6 smd: 1(-0.55,0) 2(0.55,0)
  silkscreen extent -1.25,-0.55 1.25,0.55, body extent -0.5,-0.3 0.5,0.3, height 0.2
AP1-00002 [mm]
  rect 1x0.95 smd: 1(-0.8,0) 2(0.8,0)
  silkscreen extent -1.58,-0.75 1.58,0.75, body extent -0.8,-0.4 0.8,0.4, height 0.3
AP1-00015 [mm]
  rect 1.25x2.7 smd: 1(-1.525,0) 2(1.525,0)
  silkscreen extent -0.63,-1.35 0.63,1.35, body extent -1.65,-1.25 1.55,1.25, height 0.95
AP1-00028 [mm]
  rect 3.2x1.6 smd: 1(-2.5,0) 2(2.5,0)
  silkscreen extent -3.6,-3.6 3.6,3.6, body extent -3.5,-3.3 3.5,3.3, height 5.4
AP1-00039 [mil] "Capacitor 0603 Hight 0.8mm"
  rect 30x30 smd: 1(-27.5,0) 2(27.5,0)
  silkscreen extent -54,-27 54,27, body extent -31,-16 32,16, height 12
AP1-00053 [mm] "Chip Capacitor, 2-Leads, Body 1.0x0.5mm, IPC High Density"
  rect 0.65x0.5 smd: 1(-0.475,0) 2(0.475,0)
  body extent -0.5,-0.3 0.5,0.3, height 0.2
AP1-00096 [mm] "0603 SMD capacitor footprint used by SHAPPS"
  rect 0.7x0.9 smd: 1(-0.75,0) 2(0.75,0)
  body extent -0.8,-0.4 0.8,0.4, height 0.3
AP1-00097 [mm] "0805 SMD capacitor footprint used by SHAPPS"
  rect 1x1.1 smd: 1(-0.8,0) 2(0.8,0)
  silkscreen extent -1.6,-0.85 1.6,0.85, body extent -1,-0.63 1,0.63, height 0.78
AP2-00000 [mm] "Standard 0402 SMD resistor footprint"
  rect 0.8x0.65 smd: 1(-0.6,0) 2(0.6,0)
  silkscreen extent -1.25,-0.58 1.25,0.58, body extent -0.5,-0.3 0.5,0.3, height 0.2
AP2-00001 [mm]
  rect 1x0.95 smd: 1(-0.85,0) 2(0.85,0)
  silkscreen extent -1.6,-0.72 1.6,0.72, body extent -0.8,-0.4 0.8,0.4, height 0.3
AP2-00003 [mm]
  rect 1.4x1.8 smd: 1(-1.45,0) 2(1.45,0)
  silkscreen extent -2.4,-1.15 2.4,1.15, body extent -1.6,-0.8 1.6,0.8, height 1
AP2-00011 [mm] "Chip Resistor, 2-Leads, Body 1,0x0,5mm, IPC High Density"
  rect 0.6x0.55 smd: 1(-0.5,0) 2(0.5,0)
  body extent -0.5,-0.3 0.5,0.3, height 0.2
AP2-00073 [mm] "1206 SMD resistor footprint used by SHAPPS"
  rect 0.8x1.7 smd: 1(-1.5,0) 2(1.5,0)
  silkscreen extent -0.8,-0.9 0.8,0.9, body extent -1.6,-0.82 1.6,0.78, height 1
AP2-00099 [mm] "4p sense resistor, 1206"
  rect 0.94x2.65 smd mask+0.06: 1(-0.74,0.275) 4(0.74,0.275)
  rect 0.94x0.35 smd mask+0.06: 2(-0.74,-1.425) 3(0.74,-1.425)
  silkscreen extent -0.75,-1.89 0.75,1.89, body extent -0.8,-1.6 0.8,1.6, height 0.45
AP3-00119 [mm]
  rect 0.98x3.7 smd paste-0.125: 1(-1.185,0) 2(1.185,0)
  body extent -2.15,-2.15 2.15,2.15, height 2.1
AP3-00161 [mm] "CST7030 Series SMT Current Sense Transformers"
  rect 0.75x1.6 smd: 1(-2.425,1.85) 2(-2.425,-1.85)
  rect 1.7x1.6 smd: 3(2.425,-1.15) 4(2.425,1.15)
  silkscreen extent -4.2,-2.7 3.2,3.45, body extent -3.98,-2.5 3.02,2.5, height 3
AP3-00162 [mm] "xx1038 series shielded inductor"
  rect 3.8x3.5 smd: 1(-4.25,0) 2(4.25,0)
  silkscreen extent -5.2,-5.98 5.2,5.95, body extent -5.2,-5 5.2,5, height 2.95
AP4-00012 [mm]
  rect 0.9x1.2 smd: 1(1.63,0) 2(-1.63,0)
  silkscreen extent -2.5,-1.2 2.8,1.2, body extent -1.69,-0.9 1.71,0.9, height 1.21
AP4-00048 [mm] "ESD Diode"
  rect 0.25x0.5 smd mask+0.05: 1(0.325,0)
  rect 0.25x0.5 smd paste+0 mask+0.05: 2(-0.325,0)
  Top Layer region: -0.325,0.1 -0.65,0.1 -0.65,-0.1 -0.325,-0.1
  Top Layer region: 0.325,-0.1 0.65,-0.1 0.65,0.1 0.325,0.1
  silkscreen extent -1.08,-0.47 0.89,0.5, body extent -0.5,-0.33 0.5,0.33, height 0.41
AP4-00063 [mm]
  rect 2x1.1 smd: 1(-0.95,0)
  rect 0.8x0.8 smd: 2(0.95,0)
  silkscreen extent -2.6,-1 1.65,1, body extent -1.65,-0.7 1.05,0.7, height 0.73
AP4-00084 [mm] "SOD523/SC-79 Diode"
  rect 0.7x0.5 smd: 1(-0.55,0) 2(0.55,0)
  silkscreen extent -0.9,-0.62 -0.2,0.62, body extent -0.8,-0.4 0.8,0.4, height 0.7
AP4-00160 [mm] "ROHM SML-P11 0402 LED"
  rect 0.6x0.5 smd: 1(-0.5,0) 2(0.5,0)
  silkscreen extent -1.14,-0.25 -1.05,0.25, body extent -0.5,-0.3 0.5,0.3, height 0.19
AP5-00046 [mm] "SMD SOT23 shrunk footprint for SHAPPS"
  rect 0.9x0.6 smd: 1(-1.15,0.95) 2(-1.15,-0.95) 3(1.125,0)
  silkscreen extent -0.76,-1.53 0.74,1.52, body extent -1.25,-1.46 1.23,1.46, height 1
AP5-00056 [mm] "DFN1006-3/SOT883, 3-Leads, Body 1,050x0,65mm, Pitch 0,35mm"
  rect 0.4x0.25 smd: 1(-0.35,0.225) 2(-0.35,-0.225)
  rect 0.4x0.7 smd: 3(0.35,0)
  silkscreen extent -0.92,0.34 -0.83,0.44, body extent -0.5,-0.3 0.5,0.3, height 0.49
AP5-00058 [mm] "8-lead 5.0x6.0 mm Body, PDFN"
  rect 0.56x1.06 smd: 1(-1.905,-2.775) 2(-0.635,-2.775) 3(0.635,-2.775) 4(1.905,-2.775)
  rect 0.56x0.86 smd: 5(1.905,2.975) 6(0.635,2.975) 7(-0.635,2.975) 8(-1.905,2.975)
  Top Layer region: -2.18,2.55 -2.31,2.42 -2.31,-0.815 -2.85,-0.815 -2.85,-1.165 -2.31,-1.165 -2.31,-1.35 -1.985,-1.675 2.31,-1.675 2.31,-1.165 2.85,-1.165 2.85,-0.815 2.31,-0.815 2.31,2.42 2.18,2.55
  silkscreen extent -2.87,-3.79 2.65,3.15, body extent -2.5,-3 2.5,3, height 1
AP6-00014 [mm]
  rect 1.1x0.7 smd mask+0.07: 1(-1.3,0.95) 2(-1.3,0) 3(-1.3,-0.95) 4(1.3,-0.95) 5(1.3,0.95)
  silkscreen extent -2.2,-1.75 2.2,1.75, body extent -1.5,-1.5 1.5,1.5, height 1.3
AP6-00095 [mm]
  rect 1x0.55 smd: 1(-1.2,0.95) 2(-1.2,0) 3(-1.2,-0.95) 4(1.2,-0.95) 5(1.2,0) 6(1.2,0.95)
  silkscreen extent -2,-1.75 2,1.75, body extent -1.21,-1.4 1.21,1.39, height 1.09
AP6-00418 [mm] "MLF-32 solder foot print"
  oval 0.28x0.85 smd paste-0.03 mask+0: 1(-1.746,-2.39) 2(-1.246,-2.39) 3(-0.746,-2.39) 4(-0.246,-2.39) 5(0.254,-2.39) 6(0.754,-2.39) 7(1.254,-2.39) 8(1.754,-2.39) 17(1.754,2.39) 18(1.254,2.39) 19(0.754,2.39) 20(0.254,2.39) 21(-0.246,2.39) 22(-0.746,2.39) 23(-1.246,2.39) 24(-1.746,2.39)
  oval 0.85x0.28 smd paste-0.03 mask+0: 9(2.386,-1.746) 10(2.386,-1.246) 11(2.386,-0.746) 12(2.386,-0.246) 13(2.386,0.254) 14(2.386,0.754) 15(2.386,1.254) 16(2.386,1.754) 25(-2.383,1.746) 26(-2.383,1.246) 27(-2.383,0.746) 28(-2.383,0.246) 29(-2.383,-0.254) 30(-2.383,-0.754) 31(-2.383,-1.254) 32(-2.386,-1.75)
  rect 3.4x3.4 smd paste-1.7 mask+0: 33(0.004,0)
  silkscreen extent -2.62,-3.17 2.5,2.5, body extent -2.55,-2.55 2.55,2.55, height 1
AP6-00481 [mm] "6 Pin 1.2mm X 1.2mm Thin DFN"
  rect 0.35x0.18 smd mask+0.05: 1(-0.525,0.4) 2(-0.525,0) 3(-0.525,-0.4) 4(0.525,-0.4) 5(0.525,0) 6(0.525,0.4)
  rect 0.3x0.94 smd mask+0.05: 7(0,0)
  silkscreen extent -1.06,0.63 -0.96,0.72, body extent -0.63,-0.62 0.63,0.63, height 0.6
AP6-00483 [mm] "QFN16 4x4 thermal pad"
  rect 0.8x0.35 smd: 1(-2,0.975) 2(-2,0.325) 3(-2,-0.325) 4(-2,-0.975) 9(2,-0.975) 10(2,-0.325) 11(2,0.325) 12(2,0.975)
  rect 0.35x0.8 smd: 5(-0.975,-2) 6(-0.325,-2) 7(0.325,-2) 8(0.975,-2) 13(0.975,2) 14(0.325,2) 15(-0.325,2) 16(-0.975,2)
  rect 2.5x2.5 smd mask+0.05: 17(0,0)
  silkscreen extent -2.66,-2.67 2.67,2.66, body extent -2,-2 2,2, height 0.9
AP6-00505 [mm] "X2-DFN1010, 6-Leads, Body 1,05x1,05mm, Pitch 0,35mm, IPC High Density"
  rect 0.55x0.2 smd paste-0.02 mask+0.075: 1(-0.35,0.35) 2(-0.35,0) 3(-0.35,-0.35) 4(0.35,-0.35) 5(0.35,0) 6(0.35,0.35)
  silkscreen extent -0.97,-0.7 0.55,0.7, body extent -0.53,-0.53 0.53,0.53, height 0.4
AP6-00524 [mm] "QFN44"
  oval 0.8x0.35 smd mask+0.07: 1(-4,3.25) 2(-4,2.6) 3(-4,1.95) 4(-4,1.3) 5(-4,0.65) 6(-4,0) 7(-4,-0.65) 8(-4,-1.3) 9(-4,-1.95) 10(-4,-2.6) 11(-4,-3.25) 23(4,-3.25) 24(4,-2.6) 25(4,-1.95) 26(4,-1.3) 27(4,-0.65) 28(4,0) 29(4,0.65) 30(4,1.3) 31(4,1.95) 32(4,2.6) 33(4,3.25)
  oval 0.35x0.8 smd mask+0.07: 12(-3.25,-4) 13(-2.6,-4) 14(-1.95,-4) 15(-1.3,-4) 16(-0.65,-4) 17(0,-4) 18(0.65,-4) 19(1.3,-4) 20(1.95,-4) 21(2.6,-4) 22(3.25,-4) 34(3.25,4) 35(2.6,4) 36(1.95,4) 37(1.3,4) 38(0.65,4) 39(0,4) 40(-0.65,4) 41(-1.3,4) 42(-1.95,4) 43(-2.6,4) 44(-3.25,4)
  rect 6.5x6.5 smd paste-2 mask+0.07: 45(0,0)
  silkscreen extent -4.1,-4.1 4.1,4.1, body extent -4,-4 4,4, height 1
AP6-00527 [mm] "DFN8, 3x3x0.9 mm, Microchip C04-062C, Style MF"
  rect 0.65x0.35 smd: 1(-1.55,0.975) 2(-1.55,0.325) 3(-1.55,-0.325) 4(-1.55,-0.975) 5(1.55,-0.975) 6(1.55,-0.325) 7(1.55,0.325) 8(1.55,0.975)
  rect 1.55x2.4 smd: 9(0,0)
  silkscreen extent -2,-1.6 1.6,1.65, body extent -1.5,-1.5 1.5,1.5, height 1
AP8-00137 [mm]
  rect 2.25x1 smd: 1(-2.75,2) 2(2.75,2) 3(-2.75,-2) 4(2.75,-2)
  silkscreen extent -4.25,-3.25 4.25,3.25, body extent -3.4,-3.21 3.4,3.22, height 3.47
AP8-00317 [mm] "Placement area for 18x6mm sticker"
  silkscreen extent 0,0 18,6
AP8-00676 [mm]
  rect 1.7x1.7 / inner round 1.7 / far side rect 1.7x1.7 hole 1: 1(-6.35,0)
  round 1.7 hole 1: 2(-3.81,0) 3(-1.27,0) 4(1.27,0) 5(3.81,0) 6(6.35,0)
  silkscreen extent -7.62,-1.48 7.62,1.48, body extent -7.62,-1.27 7.62,1.27, height 8.38
AP8-00870 [mil] "TP_SMT_.8mm"
  round 31.5 smd paste-39.37: 1(0,0)
AP8-00997 [mm] "SMT test point array 2x5 0.8mm, Pitch 1.27 mm"
  round 0.8 smd paste-1: 1(-2.54,-0.635) 2(-2.54,0.635) 3(-1.27,-0.635) 4(-1.27,0.635) 5(0,-0.635) 6(0,0.635)
  silkscreen extent -3.28,-1.37 -3.07,-1.17
AP8-01099 [mm] "Micro USB AB connector from Allen Creations. Signals surface mount, shield DIP"
  rrect52% 2x2.1 on Top Paste: 0(-3.69,0) 0(3.69,0)
  rrect100% 1.15x0.94 on Top Paste: 0(-2.225,2.9) 0(2.225,2.9)
  rect 0.35x1.7 smd: 1(-1.3,2.68) 2(-0.65,2.68) 3(0,2.68) 4(0.65,2.68) 5(1.3,2.68)
  rrect52% 2x2.1 hole 0.5 slot 1.1 at 90 deg copper offset 0.437,0: 6(-4.175,0)
  rrect52% 2x2.1 hole 0.5 slot 1.1 at 90 deg copper offset -0.437,0: 7(4.175,0)
  rrect100% 1.05x0.84 hole 0.54 slot 0.75 at 0 deg: 8(-2.225,2.9) 9(2.225,2.9)
  round 0 hole 0.55 unplated: 10(-2,2.05) 11(2,2.05)
  silkscreen extent -4.05,1.38 4.05,3.1, body extent -4.32,-2.65 4.33,3.25, height 2.78
AP8-01113 [mm] "Header Female Vertical 3 Way 1.27mm Pitch"
  oval 1.05x1.524 hole 0.75: 1(-1.27,0) 2(0,0) 3(1.27,0)
  silkscreen extent -2.13,-2.03 2.13,1.4, body extent -2.02,-1.52 2.02,1.52, height 8.51
AP8-01136 [mm] "THM TP Loop Red"
  round 2.8 on Top Paste: 0(0,0)
  round 2.8 hole 1.6: 1(0,0)
  silkscreen extent -1.75,-1.75 1.75,1.75, body extent -1.59,-1.59 1.59,1.59, height 8.13
AP8-01137 [mm] "THM TP Loop White"
  round 2.8 on Top Paste: 0(0,0)
  round 2.8 hole 1.6: 1(0,0)
  silkscreen extent -1.75,-1.75 1.75,1.75, body extent -1.59,-1.59 1.59,1.59, height 8.13
AP8-01138 [mm] "THM TP Loop Orange"
  round 2.8 on Top Paste: 0(0,0)
  round 2.8 hole 1.6: 1(0,0)
  silkscreen extent -1.75,-1.75 1.75,1.75, body extent -1.59,-1.59 1.59,1.59, height 8.13
AP8-01139 [mm] "THM TP Loop Yellow"
  round 2.8 on Top Paste: 0(0,0)
  round 2.8 hole 1.6: 1(0,0)
  silkscreen extent -1.75,-1.75 1.75,1.75, body extent -1.59,-1.59 1.59,1.59, height 8.13
AP8-01140 [mm] "THM TP Loop Green"
  round 2.8 on Top Paste: 0(0,0)
  round 2.8 hole 1.6: 1(0,0)
  silkscreen extent -1.75,-1.75 1.75,1.75, body extent -1.59,-1.59 1.59,1.59, height 8.13
AP8-01144 [mm] "Banana Test Connector, 4mm, Socket, RED"
  round 2.8 hole 1.8: 1(-7.75,0) 2(7.75,0)
  silkscreen extent -9.65,-5.7 11.3,5, body extent -12.7,-5.65 11.3,5.05, height 13
AP8-01145 [mm] "Banana Test Connector, 4mm, Socket, BLACK"
  round 2.8 hole 1.8: 1(-7.75,0) 2(7.75,0)
  silkscreen extent -9.65,-5.65 11.3,5, body extent -12.7,-5.65 11.3,5.05, height 13
AP8-01149 [mm] "Single Testpad, 1mm"
  round 1 smd paste-1: 1(0,0)
AP8-01159 [mm] "THM TP Loop Black"
  round 2.8 on Top Paste: 0(0,0)
  round 2.8 hole 1.6: 1(0,0)
  silkscreen extent -1.75,-1.75 1.75,1.75, body extent -1.59,-1.59 1.59,1.59, height 8.13
AP8-01163 [mm] "Rubber feet. 7.92mm Diam, 5.08mm thick"
  silkscreen extent -3.96,-3.96 3.96,3.96, body extent -3.96,-3.96 3.96,3.96, height 7.9
AP9-00044 [mm]
  rect 1x0.95 smd paste-1: 1(-0.85,0) 2(0.85,0)
  Top Layer region: -0.45,-0.15 0.45,-0.15 0.45,0.15 -0.45,0.15
  silkscreen extent -1.6,-0.72 1.6,0.72, body extent -0.8,-0.4 0.8,0.4, height 0.3

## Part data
C100 C103 C108 C313: library part A01-0806, "Ceramic capacitor, SMD 0603, X5R, 16V, 10%", Manufacturer=Murata, MPN=GRM185R61C475KE11, TemperatureRange="-55 to +85 deg C", Tolerance=10%
C101 C105 C107 C109 C110 C200 C202 C203 C204 C205 C206 C211 C300 C311 C312 C323 C324: library part A01-0664, "Ceramic capacitor, SMD 0402, X7R, 50V, 10%", Manufacturer=Murata, MPN=GRM155R71H104KE14, TemperatureRange="-55 to +125 deg C", Tolerance=10%
C102: library part A01-0334, "Ceramic Capacitors - SMD0402 6.3V, 470nF, 10%, X5R", Manufacturer=Kemet, MPN=C0402C474K9PACTU, TemperatureRange="-55 to +85℃", Tolerance=±10%
C104: library part A01-0300, "Ceramic capacitor, SMD 0402, X5R, 6.3V, +/-20%", Manufacturer=Kemet, MPN=C0402C225M9PAC, TemperatureRange="-55°C to +85°C", Tolerance=±20%
C106: library part A01-0286, "Ceramic capacitor, SMD 0402, X5R, 6.3V, +/-10% (de26942)", Manufacturer=Kemet, MPN=C0402C105K9PAC, TemperatureRange="-55 to 85 deg C", Tolerance=+/-10%
C201: library part A01-0584, "Ceramic capacitor, SMD 0603, X5R, 25V, ±10 %", Manufacturer=Murata, MPN=GRM188R61E106MA73D
C207: library part A01-0025, "Ceramic capacitor, SMD 0402, NP0, 50V, +/-5%", Manufacturer=Kemet, MPN=C0402C680J5GAC, TemperatureRange="-55 - +125 deg C", Tolerance="50V, +/-5%"
C208: library part A01-0619, "Ceramic capacitor, SMD 0402, X7R, 50V, 10%", Manufacturer=Murata, MPN=GRM155R71H472KA01J, TemperatureRange="-55°C to 125°C", Tolerance=±10%
C209: library part A01-0848, "Ceramic capacitor, SMD 0402, NP0, 50V, +/-10%", Manufacturer=Murata, MPN=GRM1555C1H131GA01D, TemperatureRange="-55 - +125 deg C", Tolerance="50V, +/-10%"
C210: library part A01-0021, "Ceramic capacitor, SMD 0402, NP0, 50V, +/-5%", Manufacturer=Murata, MPN=GRM1555C1H330JA01D, TemperatureRange="-55 - +125 deg C", Tolerance="50V, +/-5%"
C212: library part A01-0795, "Ceramic capacitor, SMD 0402, X7R, 50V, 10%", Manufacturer=Murata, MPN=GRM155R71H682KA88J, TemperatureRange="-55°C to 125°C", Tolerance=±10%
C213 C301: library part A01-0321, "Ceramic capacitor, SMD 0402, C0G, 50V, +/-5%", Manufacturer=Murata, MPN=GRM1555C1H102JA01D, Tolerance=5%
C302: library part A01-0489, "Ceramic capacitor, SMD 0603, X5R, 50V,", Manufacturer=tdk, MPN=C1608X5R1H105K, TemperatureRange="-55 to 125C", Tolerance="50V, +/-10%"
C303 C319: library part A01-0849, "47u/35V 20% Ø6.3mm, Max rippel=180mA(@120Hz), Tan=0.12", Manufacturer=Panasonic, MPN=EEE-FK1V470P, TemperatureRange="-55°C to +105°C", Tolerance="+/- 20%"
C304 C305 C306 C307: library part A01-0851, "Ceramic capacitor, SMD 0805, X7R, 35V, 10%", Manufacturer=tdk, MPN=C2012JB1V106K125AC, TemperatureRange="-25°C to +85°C", Tolerance=10%
C308 C309: library part A01-0504, "Ceramic capacitor, SMD 1210, X7R , 50V, ±10%", Manufacturer=Murata, MPN=GRM32ER71H106
C310 C322: library part A01-0524, "Ceramic capacitor, SMD 0603, X5R, 25V, 10 %, (de24925)", Manufacturer=Murata, MPN=GRM188R61E225KA12D
C314 C315: library part A01-0769, "Ceramic capacitor, SMD 1210, X7R, 25V, MLCC", Manufacturer=Murata, MPN=GRM32ER71E226KE15L, TemperatureRange="-55°C ~ 125°C", Tolerance=10%
C316 C317 C318: library part A01-0850, "Ceramic capacitor, SMD 1210, X5R, 16V, 20%", Manufacturer="Taiyo Yuden", MPN=EMK325ABJ107MM-T, TemperatureRange="-55 - +85 degC", Tolerance=20%
C320: library part A01-0103, "Ceramic capacitor, SMD 0603, X7R, 50V, ±10 %", TemperatureRange="-55 - +125 deg C", Tolerance="50V, ±10 %"
C321: library part A01-0629, "Ceramic Capacitor, SMD 0402, COG, 50V, +/-5%", Manufacturer=Murata, MPN=GRM1555C1H101JA01D, TemperatureRange="-55 °C to +125 °C", Tolerance=±5%
D100 D203: library part A10-0213, "LED, SMD 0402, Green, Wave length=569nm, 2.1mcd @ (1mA, 1.9Vf)rohm", Manufacturer=ROHM, MPN=SML-P12MTT86R, TemperatureRange="-40 to +85"
D200 D201: library part A04-0073, "SMD Schottky diode, 30V, 2A", Manufacturer=vishay, MPN=MSS2P3, TemperatureRange="- 55 to + 150 °C"
D202: library part A04-0116, "Low Capacitance ESD-Protection Diode, Cd=15pF, LLP1006-2L, 3,5A peak pulse", Manufacturer=vishay, MPN=VESD03A1B-HD1-GS08, TemperatureRange="-40°C to +125°C"
D204: library part A10-0214, "LED, SMD 0402, Red, Wave length=620nm, 2.1mcd @ (1mA, 1.7Vf)rohm", Manufacturer=ROHM, MPN=SML-P12UTT86R, TemperatureRange="-40 to +85"
D205: library part A10-0219, "LED, SMD 0402, Blue, Wave length=470nm, 25mcd @ (5mA, 2.9Vf)rohm", Manufacturer=ROHM, MPN=SMLP13BC8TT86, TemperatureRange="-40°C to +85°C"
D300: library part A04-0089, "3 A low Vf MEGA Schottky barrier rectifiter, Diodes, Vr<40V, Vf<540mV(@If=3A), SOD123W", Manufacturer=NXP, MPN=PMEG4030ER, TemperatureRange="-55°C to +150° C"
D301 D302 D303: library part A04-0102, "High-speed switching diode", Manufacturer=NXP, MPN=BAS516-115, TemperatureRange="-65°C to +150°C"
J100 J103: library part A08-2839, "USB micro AB, Surface mount signals and DIP shield", Manufacturer="Allen Creations Corp.", MPN=MU-MB0142AB2-269, TemperatureRange="-30°C to +80°C"
J101: library part A08-2568, "10-pin Testpoint Array, 0.8mm Pad, 1.27mm Pitch"
J102: library part A09-0783, "Default closed SMD strap, 0603 size"
J200: library part A08-1616, "1x6 pin header, 2.54mm pitch, Pin-in-Paste THM", Manufacturer=SAMTEC, MPN=HMTSW-106-23-F-S-237
J201: library part A08-2879, "1x3 - THM - Female Receptacle - 0.05 pitch", Manufacturer=SAMTEC, MPN=SLM-103-01-L-S
J300 J302: library part A08-2922, "Banana Test Connector, 4mm, Socket, Red, PCB Mount, 24 A, 30 VAC/ 60 VDC, Silver Plated Contacts, Red", Manufacturer=Multicomp, MPN=24.243.1
J301 J303: library part A08-2930, "Banana Test Connector, 4mm, Socket, Black, PCB Mount, 24 A, 30 VAC/ 60 VDC, Silver Plated Contacts", Manufacturer=Multicomp, MPN=24.243.2
L300: library part A03-0317, "680nH Shielded Power Inductor, 4.1x4.1x2.1mm, Isat=9.4A , Irms=8.2A , DCR=9mΩ", Manufacturer="Wurth Elektronik", MPN=744383560068, TemperatureRange="–40°C to +125°C", Tolerance=20%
